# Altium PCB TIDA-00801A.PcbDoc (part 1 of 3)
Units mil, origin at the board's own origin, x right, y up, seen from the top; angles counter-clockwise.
Board outline 5000 x 3000 mil, 6 copper layers (Top Layer, Signal Layer 1, Signal Layer 2, Signal Layer 3, Signal Layer 4, Bottom Layer), stack 60.502 mil thick; 195 components, 95 nets, 602 pads, 757 vias.
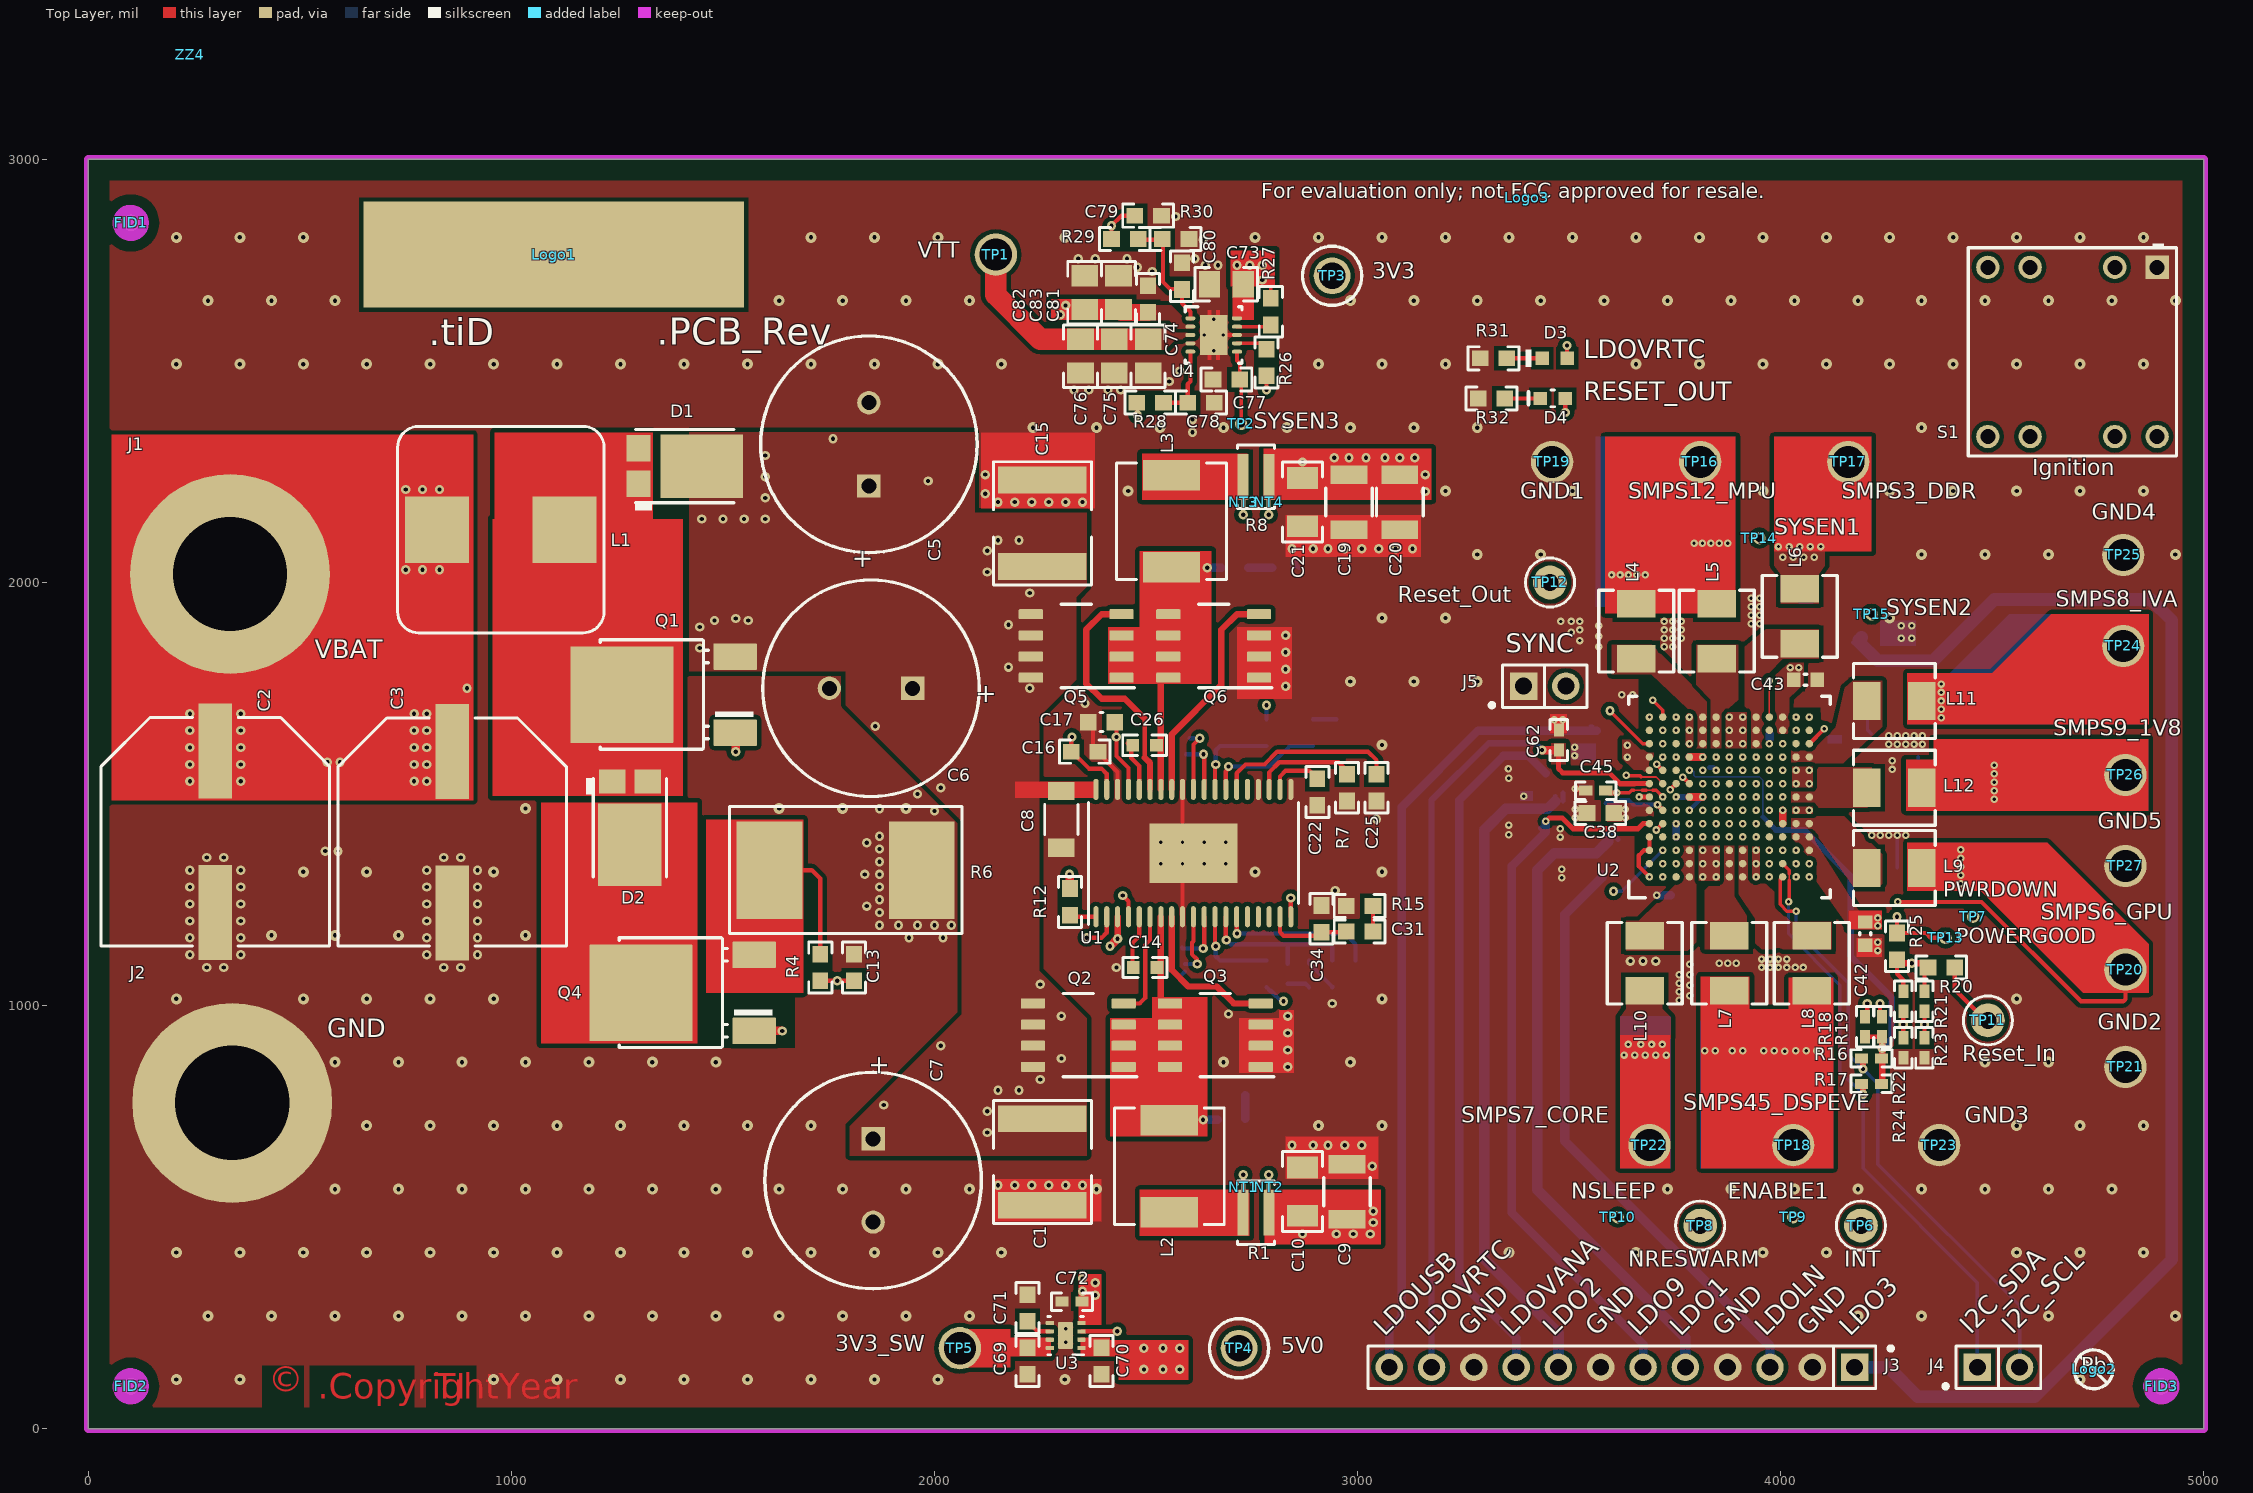
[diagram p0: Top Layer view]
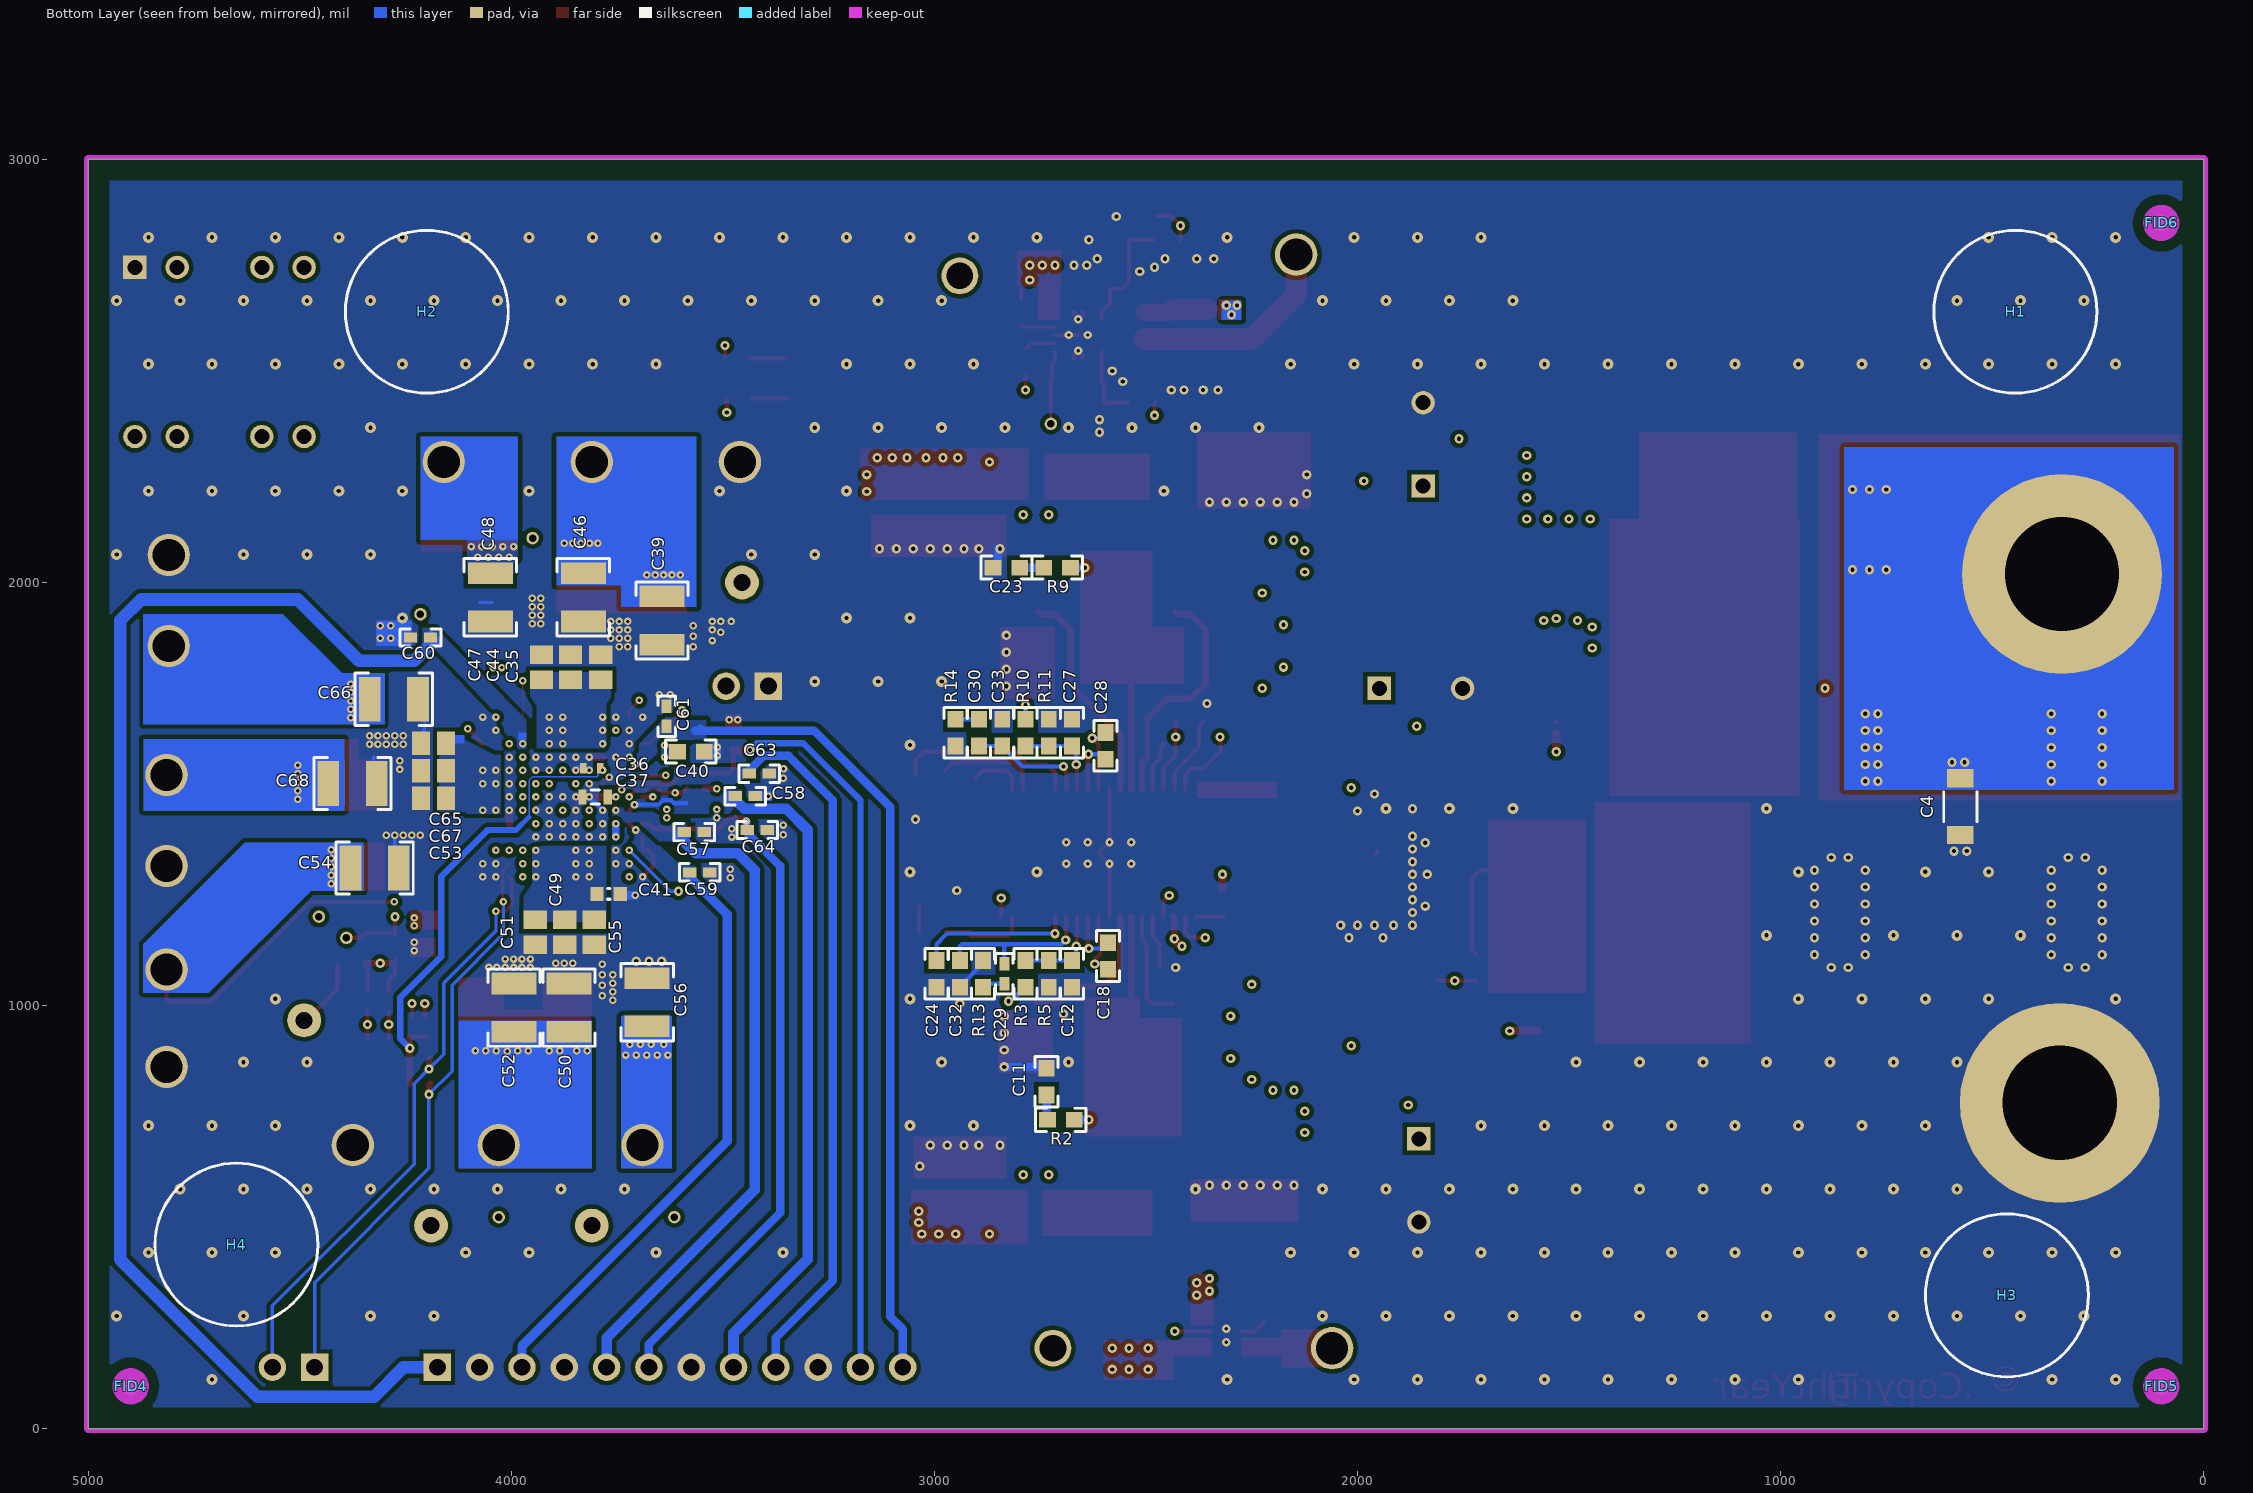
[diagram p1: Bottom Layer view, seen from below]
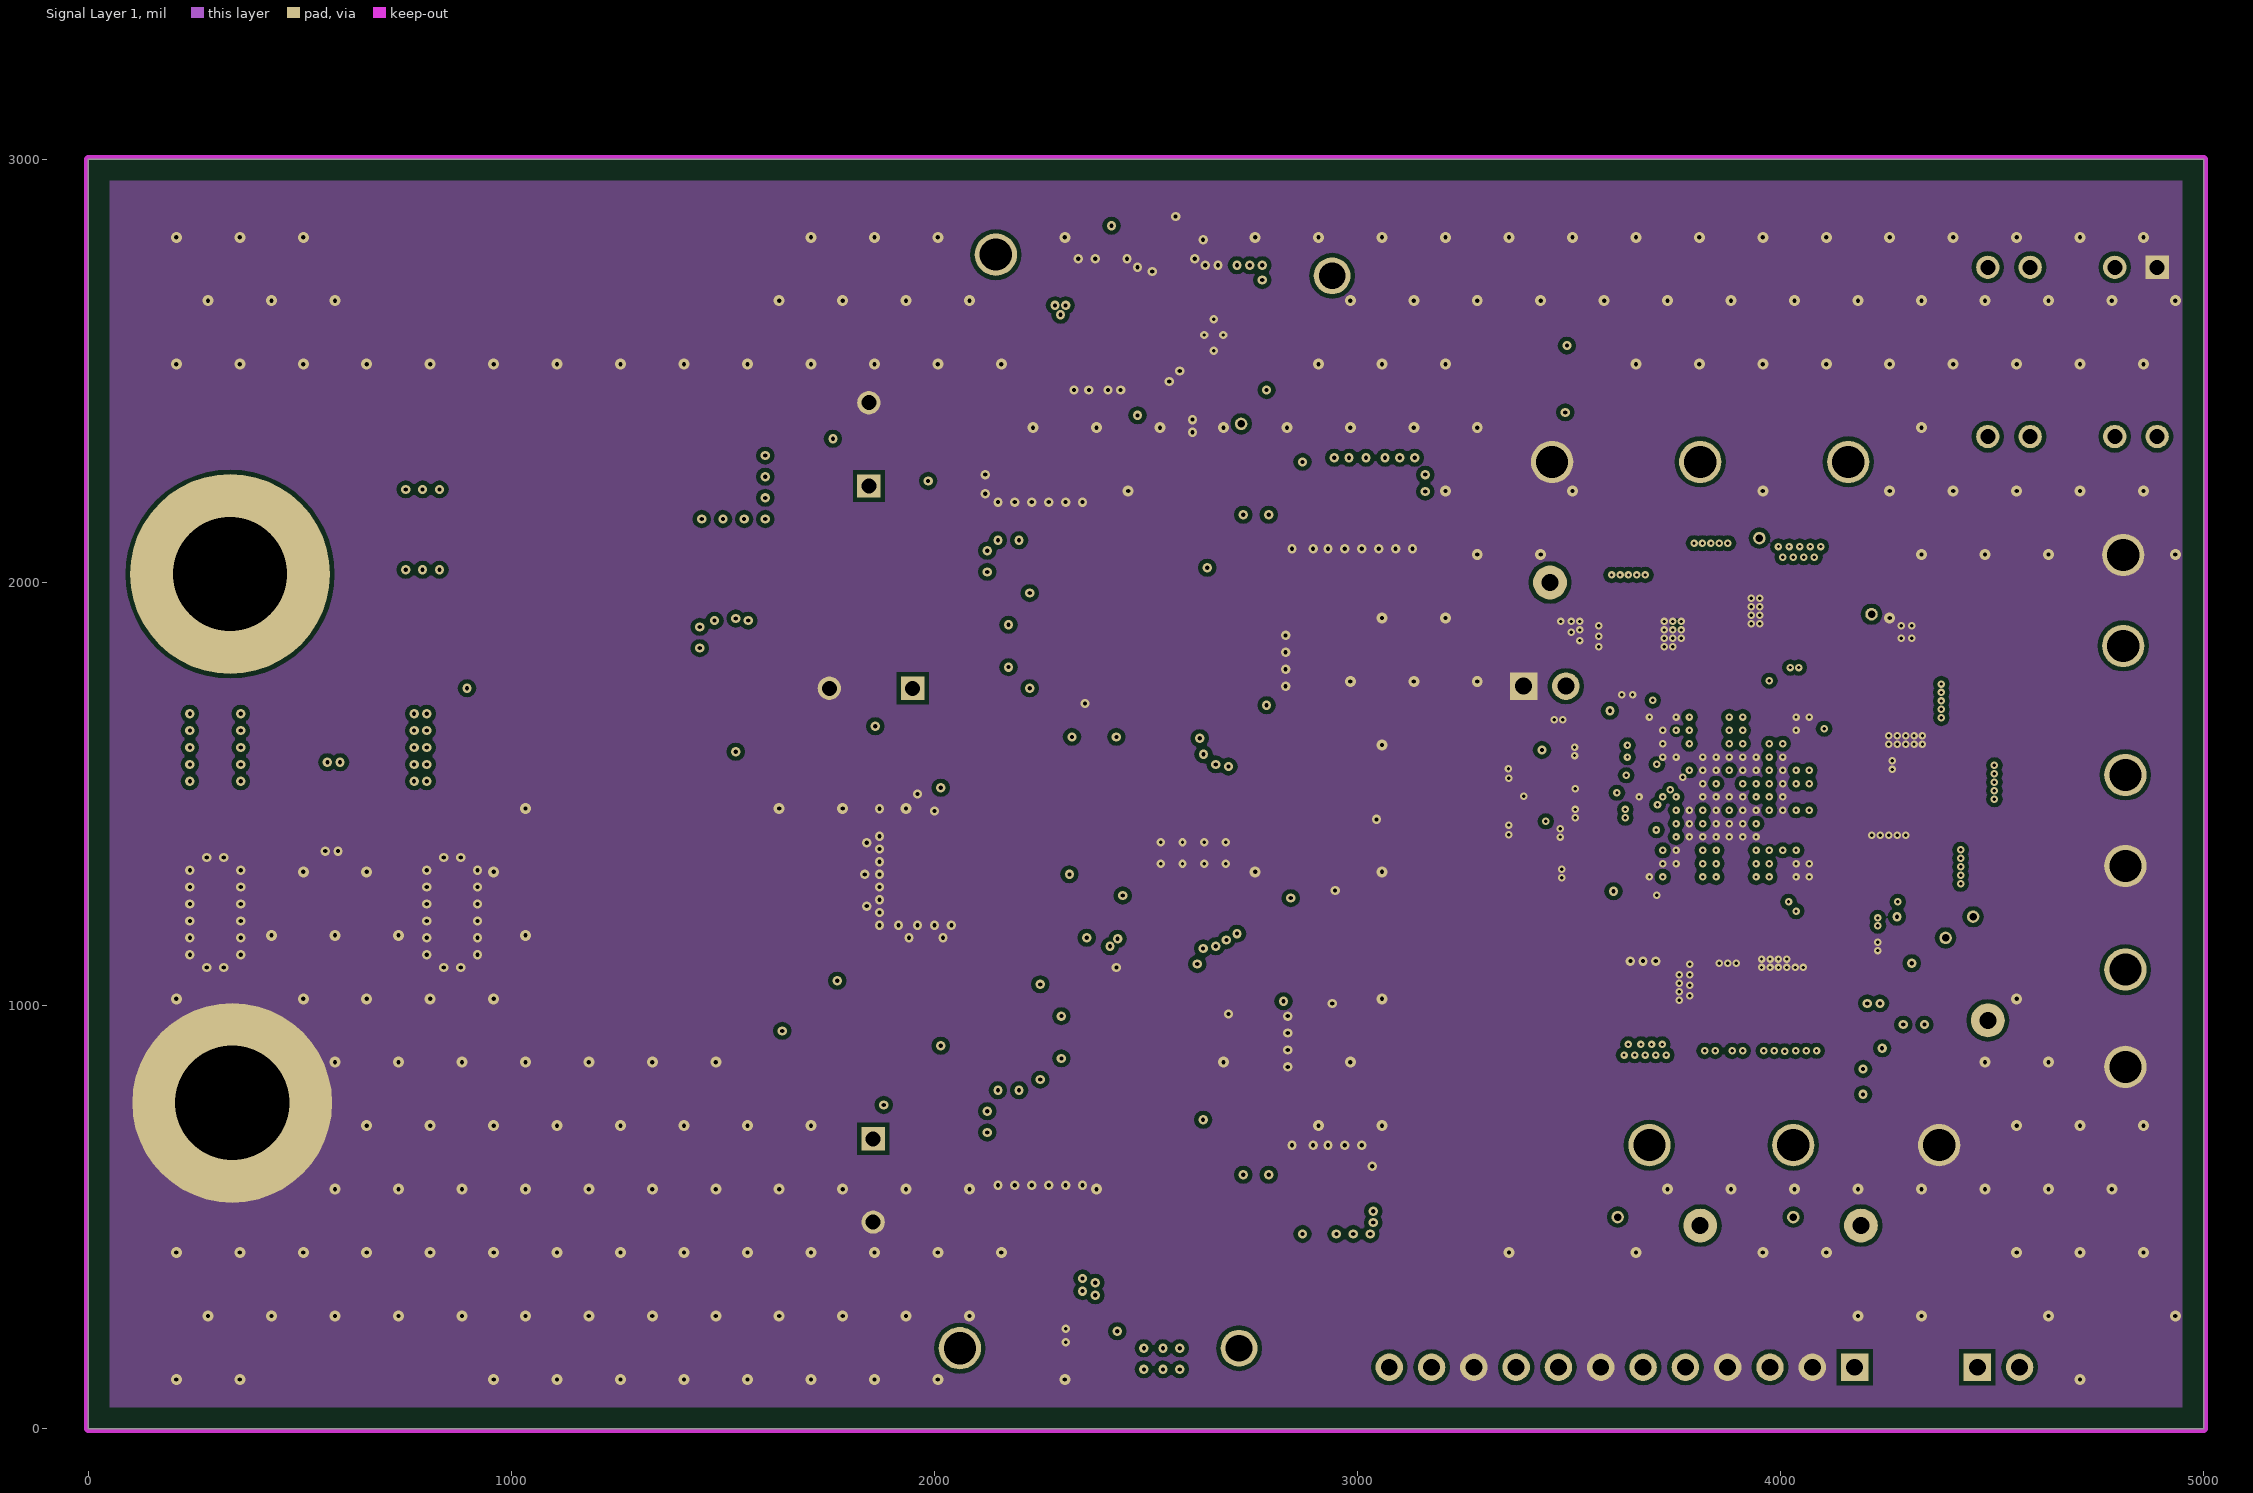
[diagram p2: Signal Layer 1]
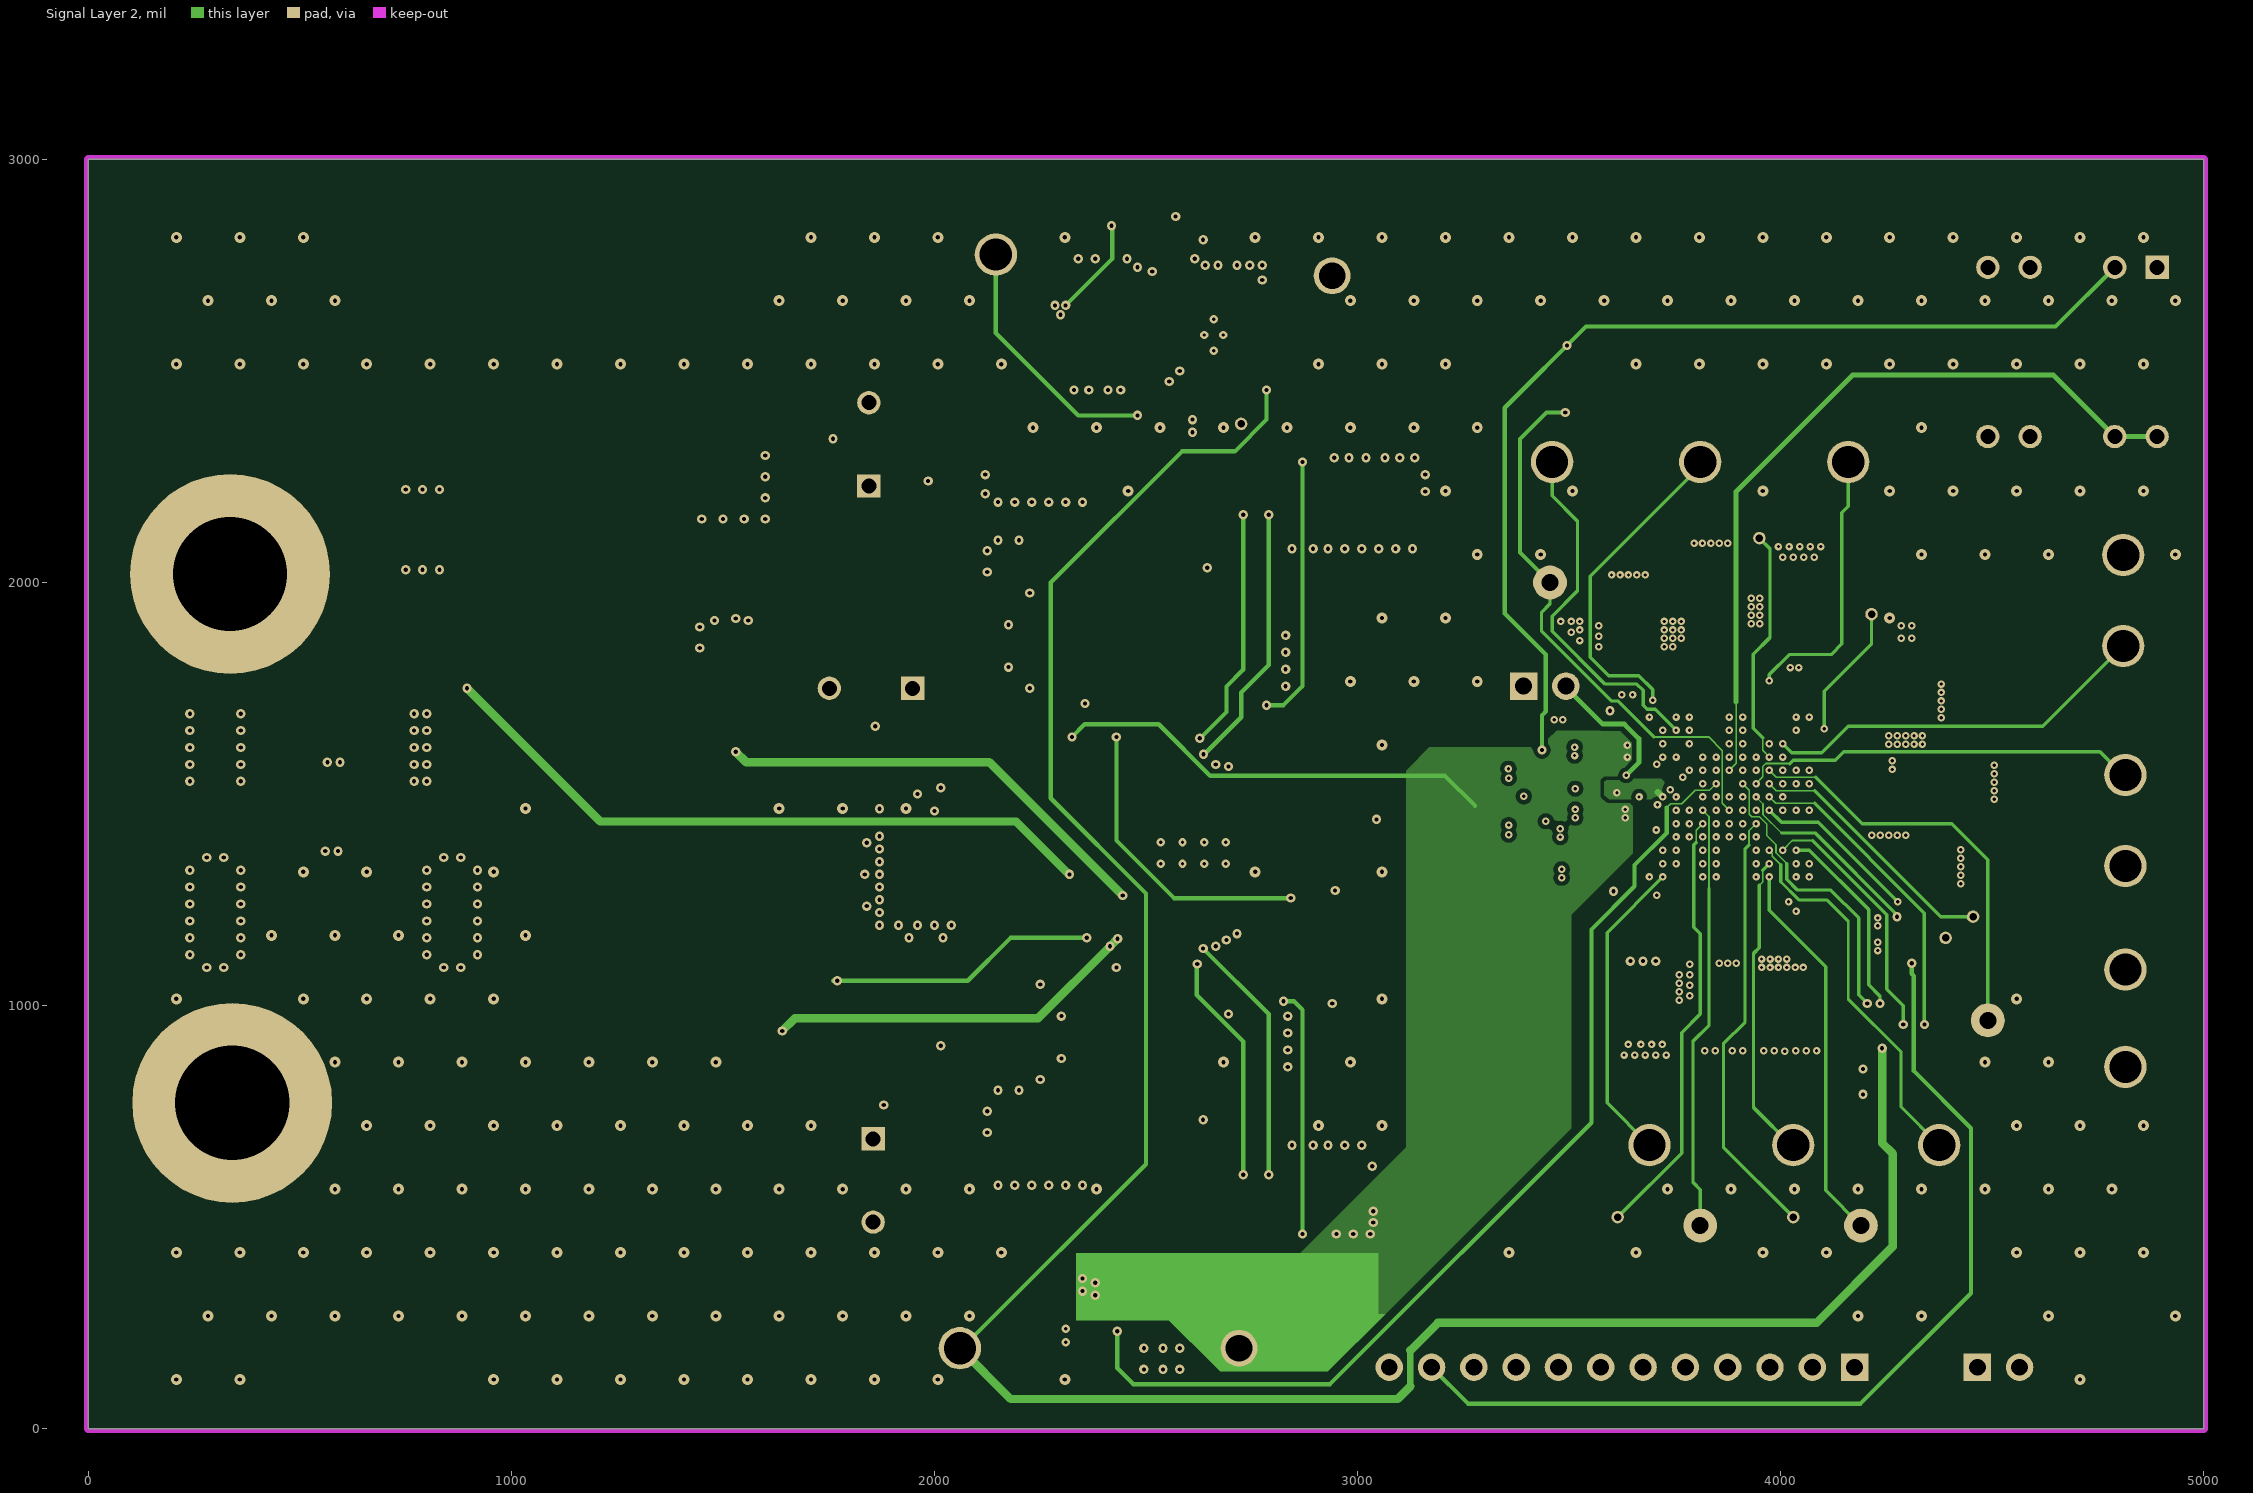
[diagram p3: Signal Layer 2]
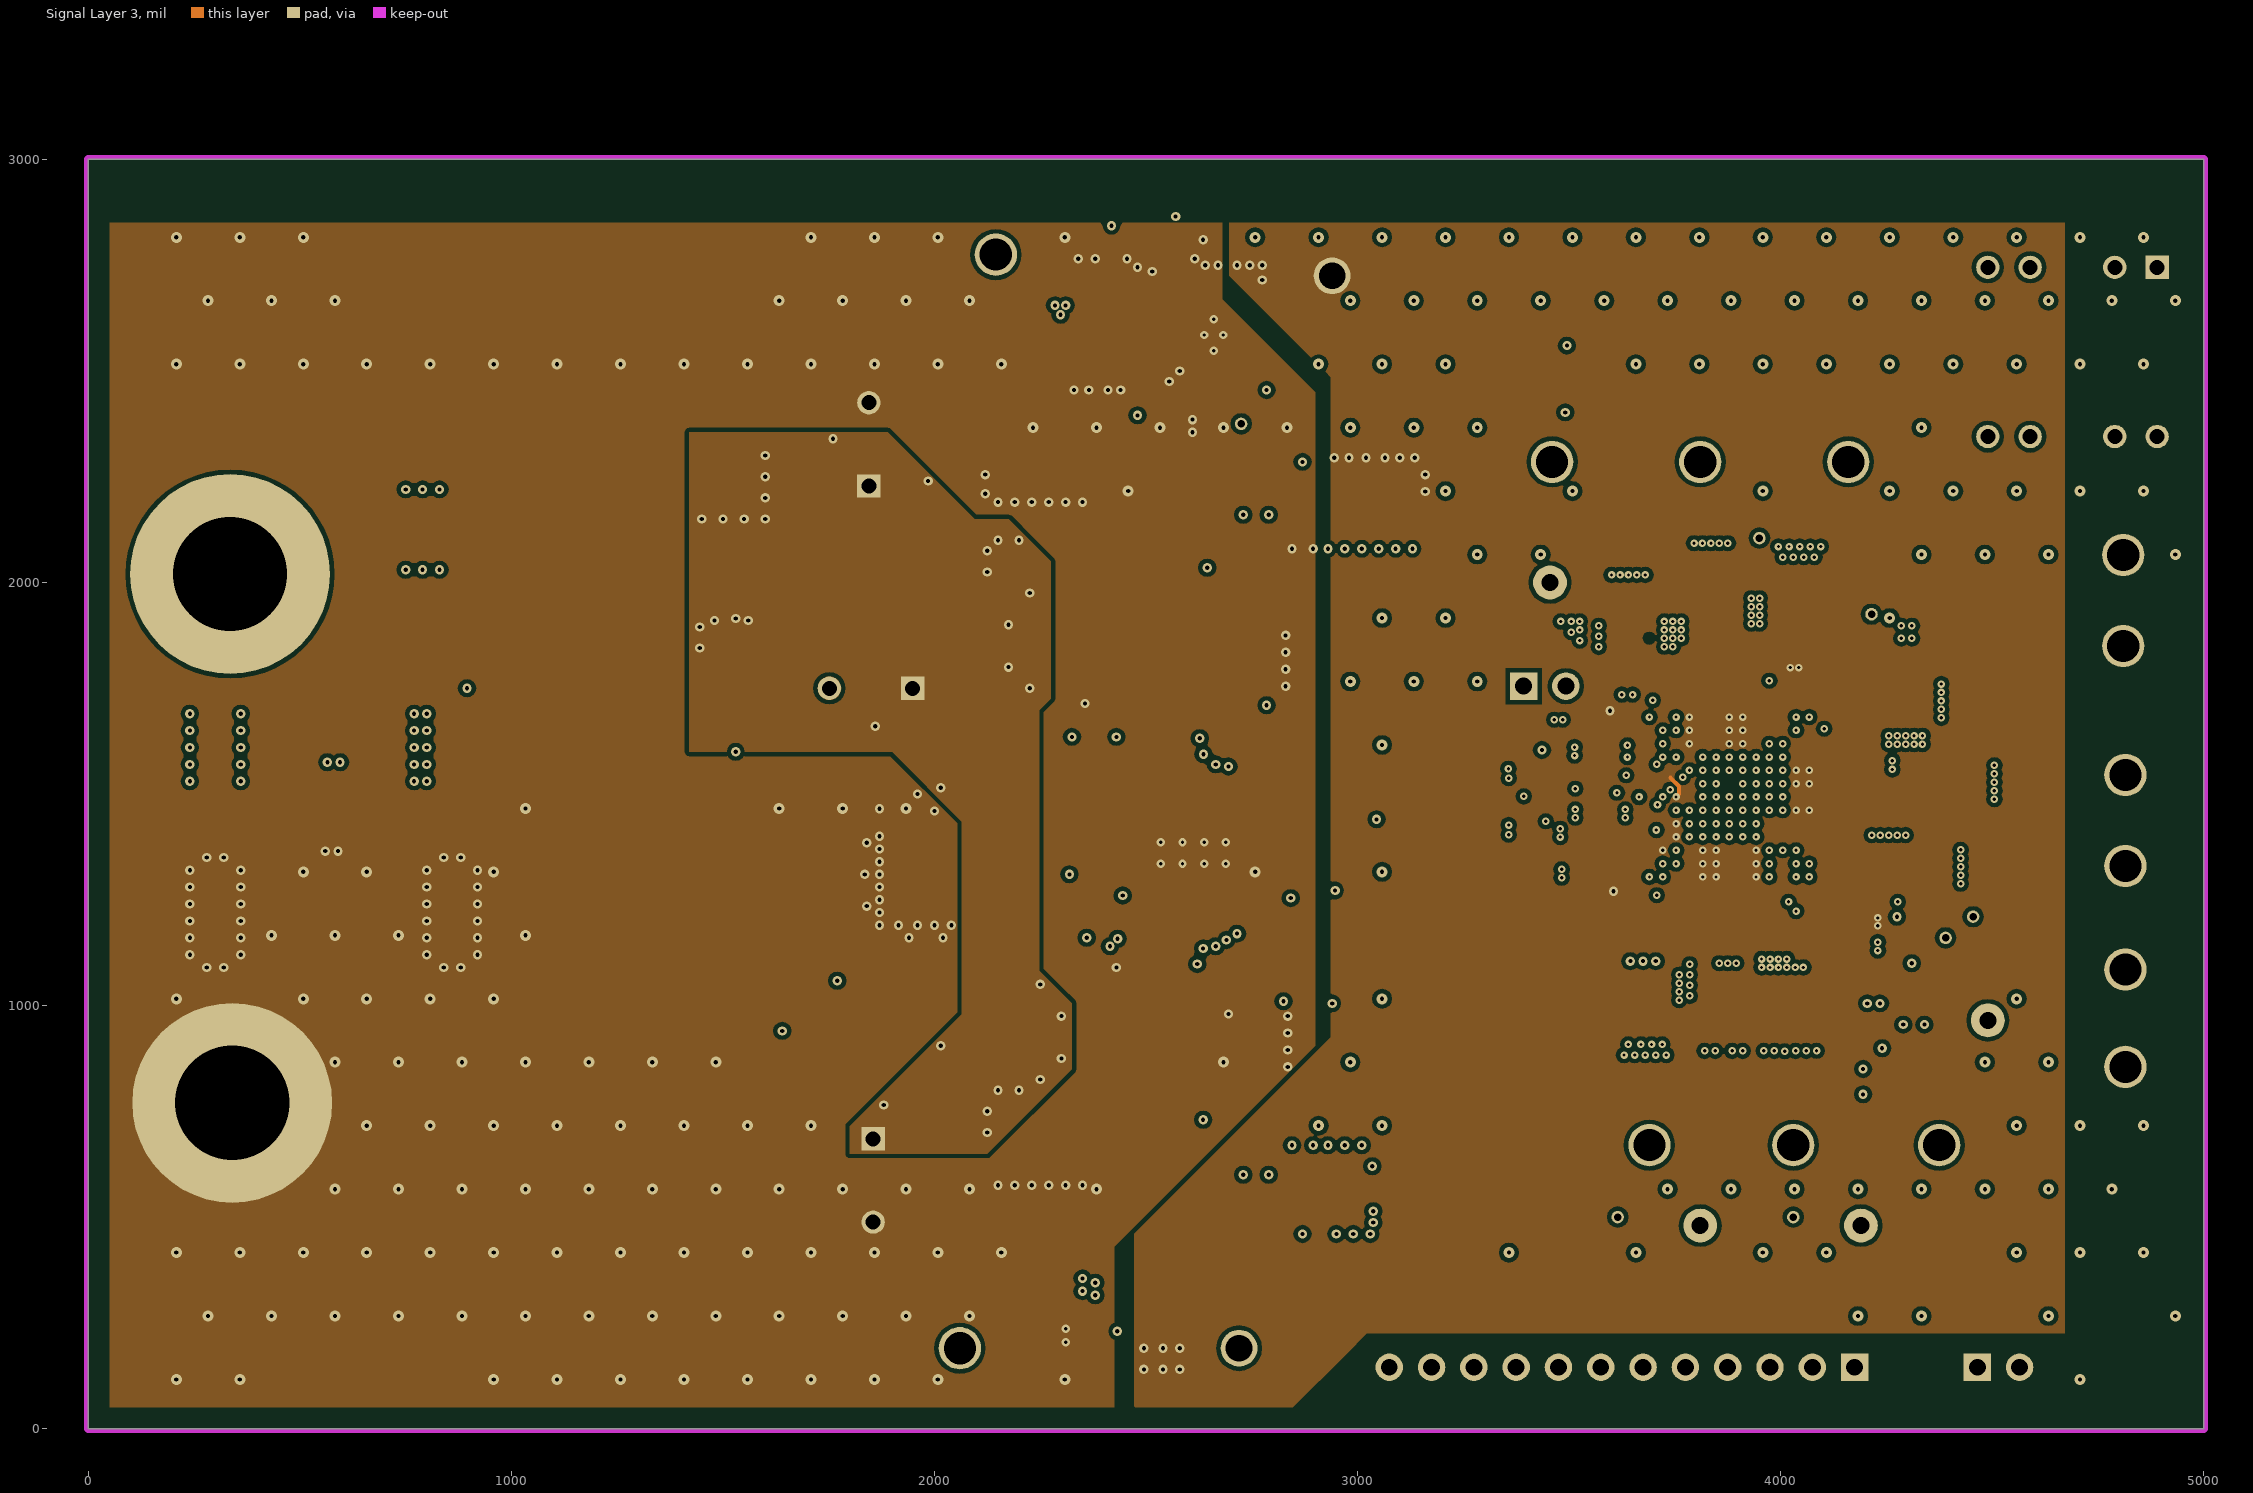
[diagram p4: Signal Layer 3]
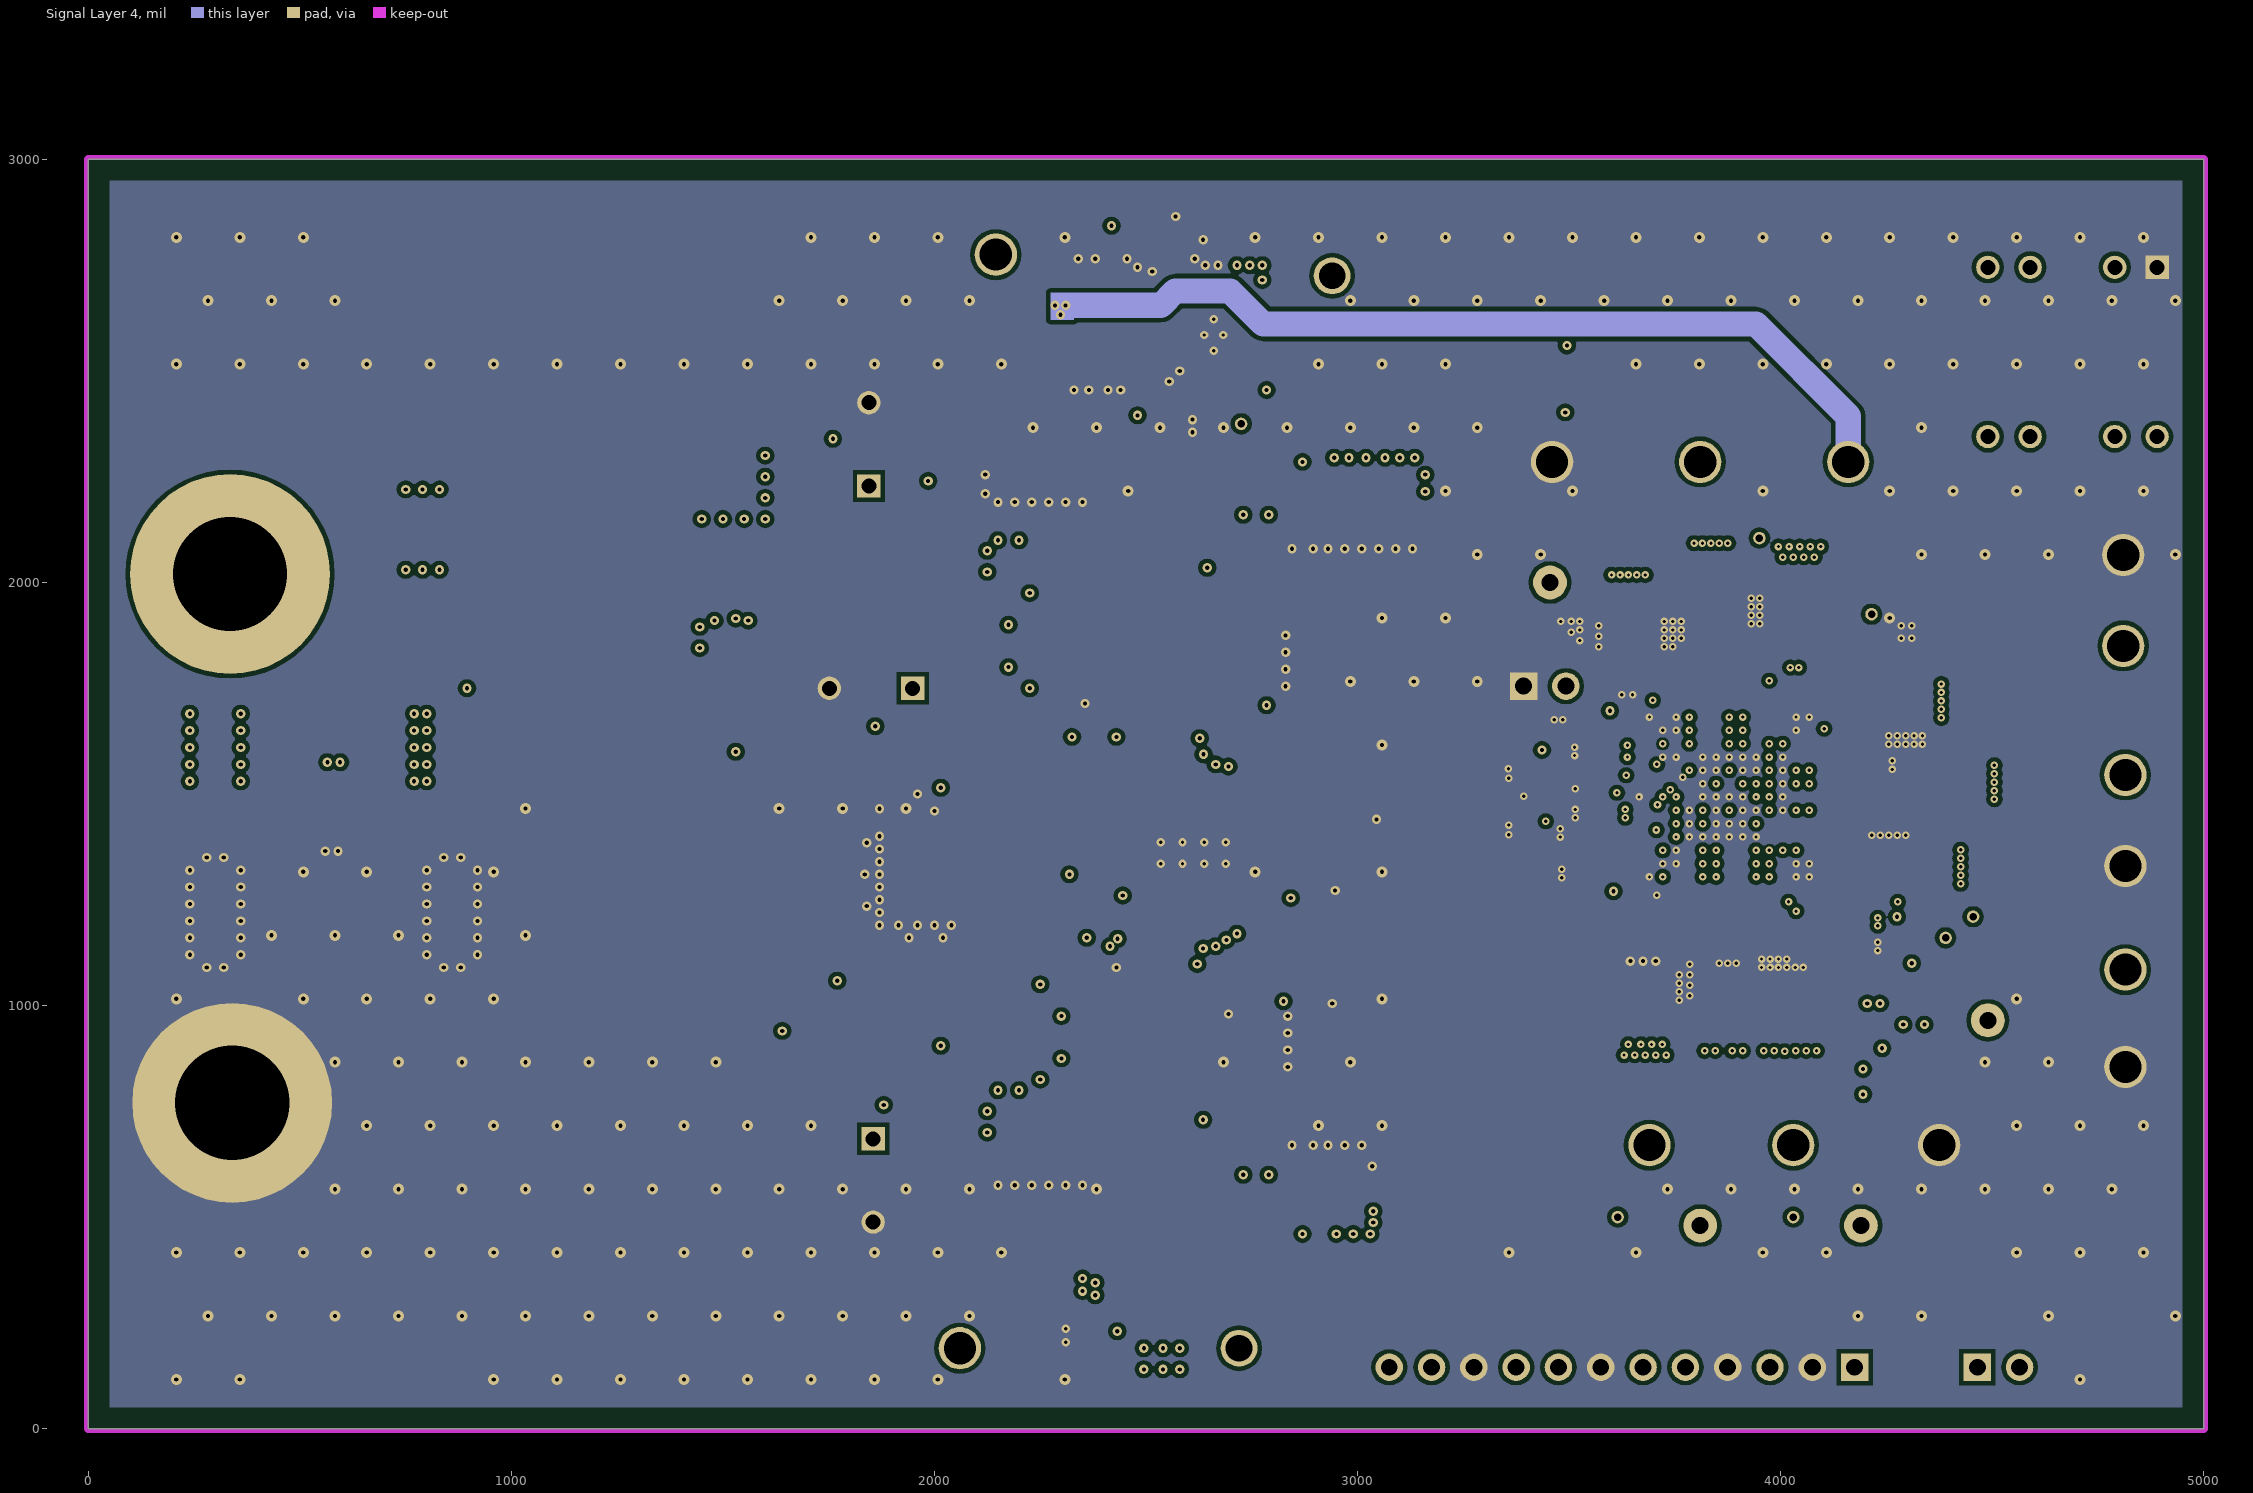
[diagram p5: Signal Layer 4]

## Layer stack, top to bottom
Top Solder: solder mask 0.4, Solder Resist, Dk 3.5
Top Layer: signal copper 1.417
Dielectric1: core 10, FR-4 High TG, Dk 4.8
Signal Layer 1: signal copper 1.417
Dielectric 2: prepreg 10, FR-4 High TG, Dk 4.8
Signal Layer 2: signal copper 1.417
Dielectric 3: core 12, FR-4 High TG, Dk 4.8
Signal Layer 3: signal copper 1.417
Dielectric 4: prepreg 10, FR-4 High TG, Dk 4.8
Signal Layer 4: signal copper 1.417
Dielectric 5: core 10, FR-4 High TG, Dk 4.8
Bottom Layer: signal copper 1.417
Bottom Solder: solder mask 0.4, Solder Resist, Dk 3.5

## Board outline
0,0 5000,0 5000,3000 0,3000

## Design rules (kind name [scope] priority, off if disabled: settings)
AcuteAngle [All] p1: minimum=4.50000000000000E+0001 checktracksonly=FALSE
AssemblyTestPointUsage [All] p1: valid=2
Clearance Clearance_Keepouts [((IsTrack Or IsArc) And Not InPoly) And IsFree and IsKeepOut vs ((IsTrack Or IsArc) And Not InPoly) And IsFree and IsKeepOut] p1: gap=0
Clearance Clearance_BoardEdge_MountingHoles [OnCopper and InComponentClass('Mounting Holes') vs IsKeepOut] p2: gap=40
Clearance Clearance_BoardEdge_Poly [OnCopper and InPoly vs IsKeepOut] p3: gap=25
Clearance Clearance_BoardEdge [OnCopper and Not InComponentClass('Logo') and not InComponentClass('FiducialMark') and not InRegion(1000,500,4000,800) and Not IsKeepout vs IsKeepOut] p4: gap=25
Clearance Clearance_Poly [InPolygon] p5: gap=10
Clearance [All] p6: gap=3.8
ComponentClearance ComponentClearance_NT [hasfootprint('Net-Tie_10milWide_30milLong')] p1: gap=0 collisioncheckmode=3 verticalgap=0 showdistances=FALSE
ComponentClearance ComponentClearance_MountingHoles_FiducialMarks [InComponentClass('Mounting Holes') vs InComponentClass('FiducialMark')] p2: gap=50 collisioncheckmode=3 verticalgap=10 showdistances=FALSE
ComponentClearance ComponentClearance_Shunt [InComponentClass('Header') vs InComponentClass('Shunt')] p3: gap=0 collisioncheckmode=3 verticalgap=0 showdistances=FALSE
ComponentClearance ComponentClearance_Logo [InComponentClass('Logo')] p4: gap=5 collisioncheckmode=3 verticalgap=5 showdistances=FALSE
ComponentClearance ComponentClearance_ScrewToNut [(HasFootprint('NY PMS 440 0025 PH')) vs (HasFootprint('Keystone_1902C'))] p5: gap=5 collisioncheckmode=3 verticalgap=10 showdistances=FALSE
ComponentClearance ComponentClearance_MountingHoles [InComponentClass('Mounting Holes')] p6: gap=150 collisioncheckmode=3 verticalgap=100000 showdistances=FALSE
ComponentClearance ComponentClearance_SmallPassives [HasFootprint('0201*') or HasFootprint('0402*') or HasFootprint('0508') or HasFootprint('0603*') or HasFootprint('0612') or HasFootprint('0805*') or HasFootprint('0815*') or HasFootprint('0830*') or HasFootprint('1206*') or HasFootprint('1210*') or HasFootprint('1808*') or HasFootprint('1812*') or HasFootprint('1825*') or HasFootprint('2010*') or HasFootprint('2220*') or HasFootprint('2225*') or HasFootprint('2512*') or HasFootprint('2728*') or HasFootprint('3518*') vs HasFootprint('0201*') or HasFootprint('0402*') or HasFootprint('0508') or HasFootprint('0603*') or HasFootprint('0612') or HasFootprint('0805*') or HasFootprint('0815*') or HasFootprint('0830*') or HasFootprint('1206*') or HasFootprint('1210*') or HasFootprint('1808*') or HasFootprint('1812*') or HasFootprint('1825*') or HasFootprint('2010*') or HasFootprint('2220*') or HasFootprint('2225*') or HasFootprint('2512*') or HasFootprint('2728*') or HasFootprint('3518*')] p7: gap=5 collisioncheckmode=3 verticalgap=5 showdistances=FALSE
ComponentClearance ComponentClearance_THtoSMT [IsThruComponent vs IsSMTComponent] p8: gap=30 collisioncheckmode=3 verticalgap=30 showdistances=FALSE
ComponentClearance ComponentClearance_THtoTH [IsThruComponent vs IsThruComponent] p9: gap=30 collisioncheckmode=3 verticalgap=30 showdistances=FALSE
ComponentClearance [All] p10: gap=20 collisioncheckmode=3 verticalgap=10 showdistances=FALSE
DiffPairsRouting [All] p1: maxlimit=100 minlimit=10 mostfreqgap=10 toplayer_minwidth=15 toplayer_maxwidth=15 toplayer_prefwidth=15 midlayer1_minwidth=15 midlayer1_maxwidth=15 midlayer1_prefwidth=15 midlayer2_minwidth=15 midlayer2_maxwidth=15 midlayer2_prefwidth=15 midlayer3_minwidth=15 midlayer3_maxwidth=15 midlayer3_prefwidth=15 midlayer4_minwidth=15 midlayer4_maxwidth=15 midlayer4_prefwidth=15 bottomlayer_minwidth=15 bottomlayer_maxwidth=15 bottomlayer_prefwidth=15 maxuncoupledlength=1000
FabricationTestPointUsage TestPointUsage [All] p1: valid=2 allowmultiple=FALSE
FabricationTestpoint Testpoint [All] p1: side=3 testpointundercomponent=TRUE minsize=40 maxsize=100 preferedsize=60 minholesize=0 maxholesize=40 preferedholesize=32 testpointgrid=1 allowsidetop=TRUE allowsidebottom=TRUE usegrid=TRUE gridtolerance=0.01
FanoutControl Fanout_LCC [IsLCC] p1: bgadir=Out bgaviamode=Centered fanoutstyle=Auto fanoutdirection=Alternating viagrid=1 // Fanout_LCC (Default Rule)
FanoutControl Fanout_BGA [IsBGA] p2: bgadir=Out bgaviamode=Centered fanoutstyle=Auto fanoutdirection=Alternating viagrid=1 // Fanout_BGA (Default Rule)
FanoutControl Fanout_Default [All] p4: bgadir=Out bgaviamode=Centered fanoutstyle=Auto fanoutdirection=Alternating viagrid=1 // Fanout_Default (Default Rule)
FanoutControl Fanout_Small [(CompPinCount < 5)] p5: bgadir=Out bgaviamode=Centered fanoutstyle=Auto fanoutdirection=OutThenIn viagrid=1 // Fanout_Small (Default Rule)
HoleSize [All] p1: absolutevalues=TRUE maxlimit=270 minlimit=7.8 maxpercent=80.000 minpercent=20.000
MinimumAnnularRing MinimumAnnularRing_ThermalPadVias [IsVia and InAnyComponent] p1: minimumring=5.91
MinimumAnnularRing [All] p2: minimumring=4.8
MinimumSolderMaskSliver MinimumSolderMaskSliver_Logo [InComponentClass('Logo') vs InComponentClass('Logo')] p1: minsoldermaskwidth=0.7
MinimumSolderMaskSliver [All] p2: minsoldermaskwidth=3.94
PlaneConnect [All] p1: planeconnectstyle=Relief reliefexpansion=10 reliefentries=4 reliefconductorwidth=10 reliefairgap=10
PolygonConnect [All] p1: connectstyle=Direct reliefconductorwidth=10 reliefentries=4 polygonreliefangle="90 Angle" airgapwidth=10
RoutingVias ThermalPadVias [IsVia and InAnyComponent] p1: holewidth=7.87 width=19.68 viastyle="Through Hole" minholewidth=7.87 minwidth=19.68 maxholewidth=12.99 maxwidth=23.62
RoutingVias [All] p2: holewidth=10 width=22 viastyle="Through Hole" minholewidth=7.8 minwidth=17 maxholewidth=40 maxwidth=65
SilkToBoardRegionClearance [Not ((IsComment or IsDesignator) And (Hide <> 'False')) and not InRegion(1000,500,4000,800)] p1 off:
SilkToSilkClearance SilkToSilkClearance_Pb-FreeLogo [(HasFootprint('Pb-Free_Overlay_Medium') OR HasFootprint('Pb-Free_Overlay_Small')) vs (HasFootprint('Pb-Free_Overlay_Medium') OR HasFootprint('Pb-Free_Overlay_Small'))] p1: silktosilkclearance=0
SilkToSilkClearance [All] p2: silktosilkclearance=3
SilkToSolderMaskClearance "Silk to Solder Mask Opening" [All] p1: minsilkscreentomaskgap=1 clearancetoexposedcopper=FALSE
SolderMaskExpansion [All] p1: expansion=1.97
UnpouredPolygon [All] p1: allowunpoured=FALSE
Width [All] p1: maxlimit=100 minlimit=4 preferedwidth=10 checkconnectedcopper=TRUE
14 further rules are at their usual default settings.

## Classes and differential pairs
component class TIDA-00801A_TPS51200: C73 C74 C75 C76 C77 C78 C79 C80 C81 C82 C83 R26 R27 R28 R29 R30 TP1 TP2 U4
component class TIDA-00801A_TPS22965: C69 C70 C71 C72 TP3 TP4 TP5 U3
component class TIDA-00801A_O9039A360: C35 C36 C37 C38 C39 C40 C41 C42 C43 C44 C45 C46 C47 C48 C49 C50 C51 C52 C53 C54 C55 C56 C57 C58 C59 C60 C61 C62 C63 C64 C65 C66 C67 C68 D3 D4 J3 J4 J5 L4 L5 L6 L7 L8 L9 L10 L11 L12 R16 R17 R18 R19 R20 R21 R22 R23 R24 R25 R31 R32 S1 TP6 TP7 TP8 TP9 TP10 TP11 TP12 TP13 TP14 TP15 TP16 TP17 TP18 TP19 TP20 TP21 TP22 TP23 TP24 TP25 TP26 TP27 U2
component class TIDA-00801A_TPS43330: C1 C2 C3 C4 C5 C6 C7 C8 C9 C10 C11 C12 C13 C14 C15 C16 C17 C18 C19 C20 C21 C22 C23 C24 C25 C26 C27 C28 C29 C30 C31 C32 C33 C34 D1 D2 J1 J2 L1 L2 L3 NT1 NT2 NT3 NT4 Q1 Q2 Q3 Q4 Q5 Q6 R1 R2 R3 R4 R5 R6 R7 R8 R9 R10 R11 R12 R13 R14 R15 U1
component class Header: J3 J4 J5
component class AssemblyNote: ZZ1 ZZ2 ZZ3 ZZ4
component class FiducialMark: FID1 FID2 FID3 FID4 FID5 FID6
component class TIDA-00801A_Hardware: FID1 FID2 FID3 FID4 FID5 FID6 H1 H2 H3 H4 Logo1 Logo2 Logo3 ZZ1 ZZ2 ZZ3 ZZ4
component class Logo: Logo1

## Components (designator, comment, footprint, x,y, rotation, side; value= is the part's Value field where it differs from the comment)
C1 "CGA9N3X7R1H106K230KB" 2220 2255,630 r270 top
C2 "EEE-TK1J221AQ" SM_RADIAL_H13 300,1410.94 r270 top
C3 "EEE-TK1J221AQ" SM_RADIAL_H13 860,1410 r270 top
C4 "CL31B105JAHNNNE" 1206_190 575,1470 r270 bottom
C5 "EEU-FC1H561" FC_1250x2500 1845,2326.57 r90 top
C6 "EEU-FC1H561" FC_1250x2500 1850,1750 r180 top
C7 "EEU-FC1H561" FC_1250x2500 1855,586.57 r270 top
C8 "CL31B105JAHNNNE" 1206_190 2300,1440 r270 top
C9 "LMK325ABJ107MMHT" 1210_280 2975,560 r90 top
C10 "C1206C105K3RACTU" 1206 2870,560 r90 top
C11 "GRM1885C1E102JA01D" 0603 2735,820 r90 bottom
C12 "GRM1885C1H470JA01D" 0603 2675,1075 r270 bottom
C13 "C0603C471K5RACTU" 0603 1810,1090 r90 top
C14 "GRM188R61E224KA88D" 0603_HV 2498,1090 r180 top
C15 "CGA9N3X7R1H106K230KB" 2220 2255,2140 r270 top
C16 "C0603C104J3RACTU" 0603 2355,1600 r180 top
C17 "GRM188R61E475KE11D" 0603_095 2395,1670 r180 top
C18 "GRM188R71E103KA01D" 0603 2590,1117 r90 bottom
C19 "LMK325ABJ107MMHT" 1210_280 2980,2190 r270 top
C20 "LMK325ABJ107MMHT" 1210_280 3100,2190 r270 top
C21 "C1206C105K3RACTU" 1206 2870,2190 r270 top
C22 "GRM188R71H102KA01D" 0603 2905,1505 r90 top
C23 "GRM188R71H102KA01D" 0603 2830,2035 r0 bottom
C24 "GRM188R71E103KA01D" 0603 2995,1075 r270 bottom
C25 "GRM188R71E103KA01D" 0603 3045,1515 r270 top
C26 "GRM188R61E224KA88D" 0603_HV 2497,1615 r180 top
C27 "GRM1885C1H470JA01D" 0603 2675,1645 r90 bottom
C28 "GRM188R71E103KA01D" 0603 2596,1614 r90 bottom
C29 "C1005C0G1E681J" 0402 2835,1075 r270 bottom
C30 "C0603X102K5RACTU" 0603 2895,1645 r90 bottom
C31 "06033C123JAT2A" 0603 3005,1175 r0 top
C32 "C1608C0G1H180J" 0603 2940,1075 r270 bottom
C33 "06035A270JAT2A" 0603 2840,1645 r90 bottom
C34 "GRM1885C1H121JA01D" 0603 2915,1205 r90 top
C35 "C2012X5R1E475K125AB" 0805L 3789,1800 r270 bottom
C36 "GCM155R71C104KA55D" 0402S 3810,1561 r180 bottom
C37 "EMK107BBJ106MA-T" 0603S 3802,1493 r0 bottom
C38 "GRM188R61C225KAAD" 0603 3574,1455 r0 top
C39 "GRM32ER71A476KE15L" 1210 3644,1910 r270 bottom
C40 "GRM188R61C225KAAD" 0603 3576,1600 r180 bottom
C41 "GRM188R61C225KAAD" 0603L 3770,1264 r180 bottom
C42 "GRM188R61C225KAAD" 0603L 4200,1170 r270 top
C43 "GRM188R61C225KAAD" 0603L 4059,1770 r0 top
C44 "C2012X5R1E475K125AB" 0805L 3860.56,1800 r270 bottom
C45 "GCM155R71C104KA55D" 0402 3563,1508 r180 top
C46 "GRM32ER71A476KE15L" 1210 3830,1965 r270 bottom
C47 "C2012X5R1E475K125AB" 0805L 3929,1800 r270 bottom
C48 "GRM32ER71A476KE15L" 1210 4050,1965 r270 bottom
C49 "C2012X5R1E475K125AB" 0805L 3874,1173 r90 bottom
C50 "GRM32ER71A476KE15L" 1210 3864.14,995 r90 bottom
C51 "C2012X5R1E475K125AB" 0805L 3944,1173 r90 bottom
C52 "GRM32ER71A476KE15L" 1210 3994,995 r90 bottom
C53 "C2012X5R1E475K125AB" 0805L 4184,1490 r180 bottom
C54 "GRM32ER71A476KE15L" 1210 4323.26,1325 r0 bottom
C55 "C2012X5R1E475K125AB" 0805L 3804,1173 r90 bottom
C56 "GRM32ER71A476KE15L" 1210 3679,1007.84 r90 bottom
C57 "GRM155R60J225ME15D" 0402 3568,1410 r180 bottom
C58 "GRM155R60J225ME15D" 0402 3447,1495 r180 bottom
C59 "GRM155R60J225ME15D" 0402 3555,1315 r180 bottom
C60 "GRM155R60J225ME15D" 0402 4215,1870 r0 bottom
C61 "GRM155R60J225ME15D" 0402 3632.95,1683.93 r90 bottom
C62 "GRM155R60J225ME15D" 0402 3476,1627.62 r90 top
C63 "GRM155R60J225ME15D" 0402 3414,1548 r180 bottom
C64 "GRM155R60J225ME15D" 0402 3419,1415 r180 bottom
C65 "C2012X5R1E475K125AB" 0805L 4184,1620 r180 bottom
C66 "GRM32ER71A476KE15L" 1210 4278,1724 r0 bottom
C67 "C2012X5R1E475K125AB" 0805L 4184,1555 r180 bottom
C68 "GRM32ER71A476KE15L" 1210 4375.5,1525 r0 bottom
C69 "GRM188R61C104KA01D" 0603 2220,160 r270 top
C70 "GRM185R61C105KE44D" 0603 2395,160 r270 top
C71 "C1608X7R1H221K" 0603 2220,285 r90 top
C72 "GRM155R61A103KA01D" 0402 2325,300 r180 top
C73 "C2012X5R1E106K125AB" 0805_HV 2690,2705 r180 top
C74 "GRM21BR70J106KE76L" 0805_HV 2505,2535 r90 top
C75 "GRM21BR70J106KE76L" 0805_HV 2425,2535 r270 top
C76 "GRM21BR70J106KE76L" 0805_HV 2345,2535 r270 top
C77 "CGA3E2X8R1E104K080AA" 0603 2690,2480 r180 top
C78 "GRM1885C2A100JA01D" 0603 2630,2425 r0 top
C79 "GRM1885C1H102FA01J" 0603 2505,2867 r180 top
C80 "GRM1885C1H102FA01J" 0603 2585,2724 r270 top
C81 "GRM1885C1H102FA01J" 0603 2505,2670 r270 top
C82 "GRM21BR70J106KE76L" 0805_HV 2355,2685 r90 top
C83 "GRM21BR70J106KE76L" 0805_HV 2435,2685 r90 top
D1 "PMEG045V150EPDAZ" SOT1289 1410,2275 r90 top
D2 "PMEG045V150EPDAZ" SOT1289 1280,1420 r0 top
D3 "SML-LX0603SRW-TR" SML-LX0603SRW_SuperRed 3466.5,2530 r180 top
D4 "LG L29K-G2J1-24-Z" "LG L29K_GREEN" 3461.5,2435 r180 top
FID1 "Fiducial" Fiducial10-20 100,2850 r0 top
FID2 "Fiducial" Fiducial10-20 100,100 r0 top
FID3 "Fiducial" Fiducial10-20 4900,100 r0 top
FID4 "Fiducial" Fiducial10-20 4900,100 r90 bottom
FID5 "Fiducial" Fiducial10-20 100,100 r90 bottom
FID6 "Fiducial" Fiducial10-20 100,2850 r90 bottom
H1 "SJ61A2" Bumpon_SJ61A2 445,2640 r180 bottom
H2 "SJ61A2" Bumpon_SJ61A2 4200,2640 r180 bottom
H3 "SJ61A2" Bumpon_SJ61A2 465,315 r180 bottom
H4 "SJ61A2" Bumpon_SJ61A2 4650,435 r180 bottom
J1 "SPC15363" Tenma_SPC15363 335,2020 r0 top
J2 "SPC15354" Tenma_SPC15354 340,770 r0 top
J3 "TSW-112-07-G-S" TSW-112-07-G-S 3625,145 r180 top
J4 "HTSW-102-07-G-S" Samtec_HTSW-102-07-G-S 4515,145 r0 top
J5 "SYNC" Samtec_HTSW-102-07-G-S 3442.48,1755 r0 top
L1 "744325180" WE-HC6 975,2125 r0 top
L2 "IHLP2525CZER100M01" IHLP-2525CZ 2555,620 r270 top
L3 "IHLP2525CZER4R7M01" IHLP-2525CZ 2560,2145 r90 top
L4 "IHLP1616ABER1R0M01" IHLP-1616AB 3659,1884.96 r90 top
L5 "IHLP1616ABER1R0M01" IHLP-1616AB 3849,1885 r90 top
L6 "IHLP1616ABER1R0M01" IHLP-1616AB 4045,1920 r90 top
L7 "IHLP1616ABER1R0M01" IHLP-1616AB 3879,1100 r270 top
L8 "IHLP1616ABER1R0M01" IHLP-1616AB 4074,1100 r270 top
L9 "IHLP1616ABER1R0M01" IHLP-1616AB 4269,1325 r0 top
L10 "IHLP1616ABER1R0M01" IHLP-1616AB 3679,1100 r270 top
L11 "IHLP1616ABER1R0M01" IHLP-1616AB 4269,1720 r0 top
L12 "IHLP1616ABER1R0M01" IHLP-1616AB 4268.96,1515 r0 top
Logo1 "Texas Instruments" TI_Stacked_SolderMask_Small 1100,2775 r0 top
Logo2 "Pb-Free Symbol" Pb-Free_Overlay_Small 4740,140 r0 top
Logo3 "FCC disclaimer" FCC_disclaimer 3400,2910 r0 top
NT1 "Net-Tie" Net-Tie_10milWide_30milLong 2730,570 r270 top net-tie
NT2 "Net-Tie" Net-Tie_10milWide_30milLong 2790,570 r270 top net-tie
NT3 "Net-Tie" Net-Tie_10milWide_30milLong 2730,2190 r90 top net-tie
NT4 "Net-Tie" Net-Tie_10milWide_30milLong 2790,2190 r90 top net-tie
Q1 "SUD50P06-15L-E3" DPAK 1395,1735 r180 top
Q2 "Si4840BDY-T1-GE3" SOIC-8 2340,930 r180 top
Q3 "Si4840BDY-T1-GE3" SOIC-8 2664,930 r180 top
Q4 "IRLR3114ZTRPBF" DPAK 1440,1030 r180 top
Q5 "Si4840BDY-T1-GE3" SOIC-8 2335,1850 r180 top
Q6 "Si4840BDY-T1-GE3" SOIC-8 2660,1850 r180 top
R1 "PRL1632-R022-F-T1" 0612 2760,510 r0 top
R2 "CRCW060310R0FKEA" 0603 2701.5,730 r180 bottom
R3 "CRCW0603432KFKEA" 0603 2785,1075 r270 bottom
R4 "ERJ-3EKF1501V" 0603 1730,1090 r270 top
R5 "CRCW060382K5FKEA" 0603 2730,1075 r90 bottom
R6 "WSR3R0150FEA" 4527 1790,1320 r180 top
R7 "RG1608P-4992-B-T5" 0603 2975,1515 r90 top
R8 "PRL1632-R015-F-T1" 0612 2760,2250 r0 top
R9 "CRCW060310R0FKEA" 0603 2710,2035 r180 bottom
R10 "CRCW0603255KFKEA" 0603 2785,1645 r90 bottom
R11 "CRCW060382K5FKEA" 0603 2730,1645 r270 bottom
R12 "CRCW06031K00JNEA" 0603 2320,1245 r270 top
R13 "RC0603JR-0739KL" 0603 2885,1075 r270 bottom
R14 "RT0603DRD0727KL" 0603 2950,1645 r90 bottom
R15 "RC0603FR-0710KL" 0603 3005,1235 r0 top
R16 "CRCW04022K20JNED" 0402 4215,875 r0 top
R17 "CRCW04022K20JNED" 0402 4215,815 r0 top
R18 "CRCW04022K20JNED" 0402 4200,950 r270 top
R19 "CRCW04022K20JNED" 0402 4240,950 r270 top
R20 "RC0603FR-0710KL" 0603 4380,1090 r0 top
R21 "RC0402JR-070RL" 0402 4340,1010 r90 top
R22 "RC0402JR-070RL" 0402 4290,1010 r90 top
R23 "RC0402JR-070RL" 0402 4340,900 r90 top
R24 "RC0402JR-070RL" 0402 4290,900 r90 top
R25 "RC0603FR-0710KL" 0603 4275,1140 r270 top
R26 "CRCW060310K0FKEA" 0603 2785,2520 r270 top
R27 "CRCW0603100KJNEA" 0603 2795,2640 r90 top
R28 "TNPW060310R0BEEA" 0603 2510,2425 r180 top
R29 "CRCW060310K0FKEA" 0603 2450,2812 r0 top
R30 "CRCW060310K0FKEA" 0603 2570,2812 r0 top
R31 "RC0603FR-0749R9L" 0603 3321.5,2530 r0 top
R32 "CRCW0603806RFKEA" 0603 3316.5,2435 r0 top
S1 "Ignition" SW_15451 4690,2545 r270 top
TP1 "VTT" Mill-Max_2505-2 2145,2775 r90 top
TP2 "SYSEN3" TP_H045P075 2725,2375 r90 top
TP3 "3V3" Keystone5006 2940,2725 r270 top
TP4 "5V0" Keystone5006 2720,190 r270 top
TP5 "3V3_SW" Mill-Max_2505-2 2060,190 r270 top
TP6 "INT" Keystone5002 4190,480 r0 top
TP7 "PWRDOWN" TP_H045P075 4455,1210 r180 top
TP8 "NRESWARM" Keystone5002 3810,480 r90 top
TP9 "ENABLE1" TP_H045P075 4030,500 r90 top
TP10 "NSLEEP" TP_H045P075 3615,500 r180 top
TP11 "Reset_In" Keystone5002 4490,965 r0 top
TP12 "Reset_Out" Keystone5002 3455,2000 r0 top
TP13 "POWERGOOD" TP_H045P075 4390,1160 r180 top
TP14 "SYSEN1" TP_H045P075 3950,2105 r180 top
TP15 "SYSEN2" TP_H045P075 4215,1925 r180 top
TP16 "SMPS12_MPU" Mill-Max_2505-2 3810,2285 r180 top
TP17 "SMPS3_DDR" Mill-Max_2505-2 4160,2285 r180 top
TP18 "SMPS45_DSPEVE" Mill-Max_2505-2 4030,670 r180 top
TP19 "GND1" Mill-Max_2505-2 3460,2285 r90 top
TP20 "SMPS6_GPU" Mill-Max_2505-2 4815,1085 r180 top
TP21 "GND2" Mill-Max_2505-2 4815,855 r90 top
TP22 "SMPS7_CORE" Mill-Max_2505-2 3690,670 r180 top
TP23 "GND3" Mill-Max_2505-2 4375,670 r0 top
TP24 "SMPS8_IVA" Mill-Max_2505-2 4810,1850 r180 top
TP25 "GND4" Mill-Max_2505-2 4810,2065 r90 top
TP26 "SMPS9_1V8" Mill-Max_2505-2 4815,1545 r180 top
TP27 "GND5" Mill-Max_2505-2 4815,1330 r90 top
U1 "TPS43330AQDAPRQ1" DAP0038B_N 2612,1360.5 r90 top
U2 "O9039A360IZWSRQ1" ZWS0169A 3879,1492.99 r90 top
U3 "TPS22965TDSGRQ1" DSG0008A 2310,220 r180 top
U4 "TPS51200QDRCRQ1" DRC0010A 2660,2585 r0 top
ZZ1 "Place washers H5 & H6 over threaded studs of banana jacks J1 & J2 before assembling onto board to increase clearance below them." AssemblyNote 240,3509 r0 top
ZZ2 "These assemblies are ESD sensitive, ESD precautions shall be observed." AssemblyNote 240,3424.11 r0 top
ZZ3 "These assemblies must be clean and free from flux and all contaminants. Use of no clean flux is not acceptable." AssemblyNote 240,3335.56 r0 top
ZZ4 "These assemblies must comply with workmanship standards IPC-A-610 Class 2, unless otherwise specified." AssemblyNote 240,3247 r0 top

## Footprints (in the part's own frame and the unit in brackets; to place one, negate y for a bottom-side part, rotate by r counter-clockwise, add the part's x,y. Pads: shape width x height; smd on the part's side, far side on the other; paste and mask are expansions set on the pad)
0402 [mm] "0402 from SM-752 data"
  rect 0.8x0.6 smd: 1(-0.6,0) 2(0.6,0)
  silkscreen extent -1.22,-0.52 1.22,0.52, body extent -0.55,-0.3 0.55,0.3, height 0.6
0402S [mil] "Based on C0402S footprint from PADS legacy"
  rect 15x24 smd mask+0: 1(-20,0) 2(20,0)
  body extent -22,-12 22,12, height 24
0603 [mm] "0603 from SM-752 data"
  rect 1x0.95 smd: 1(-0.8,0) 2(0.8,0)
  silkscreen extent -1.52,-0.69 1.52,0.69, body extent -0.87,-0.47 0.87,0.47, height 0.85
0603_095 [mm] "0603_095"
  rect 1x1 smd: 1(-0.8,0) 2(0.8,0)
  silkscreen extent -0.1,-0.58 0.1,0.58, body extent -0.87,-0.48 0.87,0.48, height 0.95
0603_HV [mil] "Ernesto recommended land pattern.  26 mil between pads."
  rect 30x30 smd: 1(-28,0) 2(28,0)
  silkscreen extent -52,-24 52,24, body extent -34,-19 34,19, height 33
0603L [mm] "0603 from SM-752 data"
  rect 0.8x0.85 smd: 1(-0.7,0) 2(0.7,0)
  silkscreen extent -0.07,-0.33 0.07,0.33, body extent -0.87,-0.47 0.87,0.47, height 1
0603S [mil] "0603 from SM-752 data"
  rect 20x35 smd mask+0: 1(-30,0) 2(30,0)
  silkscreen extent -10,-17 10,17, body extent -34,-19 34,19, height 33
0612 [mm] "Panasonic recommended land pattern, fb97d03ed01.pdf dated April 2008"
  rect 0.65x2.75 smd: 1(-0.775,0) 2(0.775,0)
  silkscreen extent -1.1,-1.9 1.1,1.9, body extent -0.9,-1.7 0.9,1.7, height 0.85
0805_HV [mil] "0805 with 30mil clearance between pads"
  rect 50x63 smd: 1(-40,0) 2(40,0)
  silkscreen extent -74,-40 74,40, body extent -43,-29 43,29, height 57
0805L [mm] "0805 from SM-752 data"
  rect 1.1x1.4 smd: 1(-0.75,0) 2(0.75,0)
  body extent -1.1,-0.72 1.1,0.72, height 1.45
1206 [mm] "1206 from SM-752 data"
  rect 1.3x1.85 smd: 1(-1.45,0) 2(1.45,0)
  silkscreen extent -2.4,-1.21 2.4,1.21, body extent -1.7,-0.9 1.7,0.9, height 1.35
1206_190 [mm] "1206_190"
  rect 1.1x1.6 smd: 1(-1.7,0) 2(1.7,0)
  silkscreen extent -0.9,-1 0.9,1, body extent -1.75,-0.95 1.75,0.95, height 1.9
1210 [mm] "1210 from SM-752 data"
  rect 1.3x2.7 smd: 1(-1.45,0) 2(1.45,0)
  silkscreen extent -2.32,-1.57 2.32,1.57, body extent -1.7,-1.35 1.7,1.35, height 1.35
1210_280 [mm] "SMD, 2-Leads, Body 3.6x2.8mm, Height 2.8mm"
  rect 1.1x2.2 smd: 1(-1.65,0) 2(1.65,0)
  silkscreen extent -0.84,-1.4 0.84,1.4, body extent -1.8,-1.4 1.8,1.4, height 2.8
2220 [mm] "Chip Capacitor, Body 5.7x5.0mm, IPC Medium Density"
  rect 1.6x5.3 smd: 1(-2.6,0) 2(2.6,0)
  silkscreen extent -3.69,-2.94 3.69,2.94, body extent -2.95,-2.62 2.95,2.62, height 1.35
4527 [mil] "Vishay recommended land pattern"
  rect 155x230 smd: 1(-180,0) 2(180,0)
  silkscreen extent -275,-150 275,150, body extent -228,-138 228,138, height 96
AssemblyNote [mil] "Assembly Note"
Bumpon_SJ61A2 [mil] "3M Hemispherical Bumpon transparent"
  round 1 on Mech4: 0(0,0)
  silkscreen extent -192,-192 192,192, body extent -191,-192 193,192, height 250
DAP0038B_N [mil] "HTSSOP-38 Normal Density"
  oval 50x12 smd: 1(-150.5,230.32) 2(-150.5,204.73) 3(-150.5,179.14) 4(-150.5,153.55) 5(-150.5,127.95) 6(-150.5,102.36) 7(-150.5,76.77) 8(-150.5,51.18) 9(-150.5,25.59) 10(-150.5,0) 11(-150.5,-25.59) 12(-150.5,-51.18) 13(-150.5,-76.77) 14(-150.5,-102.36) 15(-150.5,-127.95) 16(-150.5,-153.55) 17(-150.5,-179.14) 18(-150.5,-204.73) 19(-150.5,-230.32) 20(150.5,-230.32) 21(150.5,-204.73) 22(150.5,-179.14) 23(150.5,-153.55) 24(150.5,-127.95) 25(150.5,-102.36) 26(150.5,-76.77) 27(150.5,-51.18) 28(150.5,-25.59) 29(150.5,0) 30(150.5,25.59) 31(150.5,51.18) 32(150.5,76.77) 33(150.5,102.36) 34(150.5,127.95) 35(150.5,153.55) 36(150.5,179.14) 37(150.5,204.73) 38(150.5,230.32)
  rect 140.55x208.27 smd: 39(0,0)
  silkscreen extent -169,-248 120,248, body extent -163,-251 165,251, height 47
DPAK [mm] "D-PAK, 3-Pads, Body 6.22x6.73mm (max), TO-252AA using nominal STEP model"
  rrect6% 2.6x1.6 smd: 1(-3.4,2.28) 3(-3.4,-2.28)
  rrect2% 6.2x5.8 smd paste-2.9: 4(3.4,0)
  silkscreen extent -4.5,-3.3 4.7,3.28, body extent -3.86,-3.29 5.84,3.29, height 2.48
DRC0010A [mm] "SON, 10-Leads, Body 3x3mm, Pitch 0.5mm, Thermal Pad 2.4x1.65mm, TI Recommended"
  oval 0.6x0.24 smd: 1(-1.4,1) 2(-1.4,0.5) 3(-1.4,0) 4(-1.4,-0.5) 5(-1.4,-1) 6(1.4,-1) 7(1.4,-0.5) 8(1.4,0) 9(1.4,0.5) 10(1.4,1)
  rect 1.65x2.4 smd paste-0.825: 11(0,0)
  Top Layer region: 0.135,-1.5 0.365,-1.5 0.365,-1.1 0.135,-1.1
  Top Layer region: -0.135,-1.1 -0.365,-1.1 -0.365,-1.5 -0.135,-1.5
  Top Layer region: -0.135,1.5 -0.365,1.5 -0.365,1.1 -0.135,1.1
  Top Layer region: 0.135,1.1 0.365,1.1 0.365,1.5 0.135,1.5
  silkscreen extent -1.7,-1.7 1.7,1.7, body extent -1.55,-1.55 1.55,1.55, height 1.01
DSG0008A [mm] "SON, 8-Leads, Body 2x2mm, Pitch 0.5mm, Thermal Pad 1.6x0.9mm, TI Recommended"
  rrect40% 0.5x0.25 smd: 1(-0.95,0.75) 2(-0.95,0.25) 3(-0.95,-0.25) 4(-0.95,-0.75) 5(0.95,-0.75) 6(0.95,-0.25) 7(0.95,0.25) 8(0.95,0.75)
  rrect11% 0.9x1.6 smd paste-0.45: 9(0,0)
  silkscreen extent -1.07,-1.15 1.07,1.15, body extent -1.05,-1.05 1.05,1.05, height 0.8
FC_1250x2500 [mm] "TH, 2-Leads, Dia 12.5mm, Lead Spacing 5mm"
  rect 1.4x1.4 hole 0.9: 1(-2.5,0)
  round 1.4 hole 0.9: 2(2.5,0)
  silkscreen extent -6.5,-6.5 6.5,6.5, body extent -6.45,-6.49 6.49,6.49, height 27.01
FCC_disclaimer [mil]
Fiducial10-20 [mm]
  round 1 smd mask+0.5: 1(0,0)
  Top Layer keep-out circle w1.178: c0,0 r0.5
IHLP-1616AB [mm] "Vishay Dale recommended land pattern.  Document 34261 rev 12-Sept-13"
  rect 1.65x2.3 smd: 1(-1.65,0) 2(1.65,0)
  silkscreen extent -2.45,-2.25 2.45,2.25, body extent -2.35,-2.16 2.35,2.16, height 1.2
IHLP-2525CZ [mm] "Vishay Dale recommended land pattern.  Document 34190 rev 10-Aug-06"
  rect 1.83x3.43 smd: 1(-2.77,0) 2(2.77,0)
  silkscreen extent -3.5,-3.3 3.5,3.3, body extent -3.62,-3.36 3.62,3.36, height 3
Keystone5002 [mil] "For Keystone 500x miniature loop terminals"
  round 80 hole 40: 1(0,0)
  silkscreen extent -58,-58 58,58, body extent -49,-49 49,49, height 182
Keystone5006 [mil] "Keystone Compact loops"
  round 87 hole 63: 1(0,0)
  silkscreen extent -70,-70 70,70, body extent -63,-63 62,63, height 225
"LG L29K_GREEN" [mm] "OSRAM"
  rect 0.8x0.8 smd paste-0.4: 1(-0.75,0) 2(0.75,0)
  silkscreen extent -0.1,-0.5 1.45,0.5, body extent -0.9,-0.45 0.9,0.45, height 0.67
Mill-Max_2505-2 [mil] "Mill-Max"
  round 100 hole 76 paste+0: 1(0,0)
  body extent -62,-63 62,62, height 187
Net-Tie_10milWide_30milLong [mil] "10mil net tie, no solder mask opening, no solder paste"
  rect 30x10 smd paste-5 mask-5: 1(-15,0) 2(15,0)
Pb-Free_Overlay_Small [mil]
  silkscreen extent -46,-46 46,46
Samtec_HTSW-102-07-G-S [mm] "Samtec 100mil, 1x2, 230 mil above insulator"
  rect 1.65x1.65 hole 1.016 mask+0: 1(-1.27,0)
  round 1.65 hole 1.016 mask+0: 2(1.27,0)
  silkscreen extent -3.3,-1.27 2.54,1.27, body extent -2.54,-1.27 2.54,1.27, height 8.38
SM_RADIAL_H13 [mm] "12.5 x 13.5mm:  Panasonic H13"
  rect 5.7x2 smd: 1(-4.85,0) 2(4.85,0)
  silkscreen extent -6.85,-6.85 6.85,6.85, body extent -6.85,-6.85 6.85,6.85, height 14
SML-LX0603SRW_SuperRed [mm] "Lumex Opto/Components Inc"
  rect 0.8x0.8 smd: 1(-0.75,0) 2(0.75,0)
  silkscreen extent 1.4,-0.53 1.78,0.53, body extent -0.92,-0.53 0.92,0.53, height 1.1
SOIC-8 [mm] "duplicate of SO-8.  SOIC, 8-Leads, Body 5.0x4.0mm (max), Pitch 1.27mm, IPC Medium Density"
  rrect17% 1.45x0.6 smd: 1(-2.725,1.905) 2(-2.725,0.635) 3(-2.725,-0.635) 4(-2.725,-1.905) 5(2.725,-1.905) 6(2.725,-0.635) 7(2.725,0.635) 8(2.725,1.905)
  silkscreen extent -3.5,-2.5 0.9,2.5, body extent -3,-2.45 3,2.45, height 1.63
SOT1289 [mm] "SMD, 3-Leads, Body 4.3x5.8mm"
  rect 1.6x1.44 smd paste-0.8 mask+0.1: 1(-1.065,2.78) 2(1.065,2.78)
  rect 3.8x4.96 smd paste-2.48 mask+0.1: 3(0,-1.02)
  silkscreen extent -2.65,-2.95 2.2,2.99, body extent -2.2,-2.95 2.2,2.95, height 0.87
SW_15451 [mm] "TH, 8-Leads, Body 12.6x12.6mm"
  rect 1.4x1.4 hole 0.9: 1(-5.08,5.08)
  round 1.4 hole 0.9: 2(5.08,5.08) 3(-5.08,2.54) 4(5.08,2.54) 5(-5.08,-2.54) 6(5.08,-2.54) 7(-5.08,-5.08) 8(5.08,-5.08)
  silkscreen extent -6.5,-6.25 6.25,6.25, body extent -6.25,-6.25 6.25,6.25, height 15.64
Tenma_SPC15354 [mm] "Insulated Banana Jack, Black"
  round 12 hole 6.858: 1(0,0)
  body extent -6.3,-6.34 6.35,6.34, height 8.8
Tenma_SPC15363 [mm] "Insulated Banana Jack, Red"
  round 12 hole 6.858: 1(0,0)
  body extent -6.3,-6.34 6.35,6.34, height 8.8
TI_Stacked_SolderMask_Small [mil]
  rect 900x250 smd paste-125 mask-125: 0(0,0)
TP_H045P075 [mm] "TP_H0.45P0.75"
  round 0.75 hole 0.45: 1(0,0)
TSW-112-07-G-S [mm] "Samtec 100mil, 1x12, 230 mil above insulator"
  rect 1.65x1.65 hole 1.016 mask+0: 1(-13.97,0)
  round 1.65 hole 1.016 mask+0: 2(-11.43,0) 3(-8.89,0) 4(-6.35,0) 5(-3.81,0) 6(-1.27,0) 7(1.27,0) 8(3.81,0) 9(6.35,0) 10(8.89,0) 11(11.43,0) 12(13.97,0)
  silkscreen extent -16.27,-1.27 15.24,1.27, body extent -15.24,-1.27 15.24,1.27, height 8.38
WE-HC6 [mm] "Wurth Electronik recommended land pattern"
  rect 3.85x4 smd: 1(-3.825,0) 2(3.825,0)
  silkscreen extent -6.2,-6.2 6.2,6.2, body extent -5.77,-5.37 5.75,5.35, height 5
ZWS0169A [mm] "BGA, 169-Leads, Body 12.00x12.00mmx1.40mm, Pitch 0.80mm"
  round 0.45 smd: A1(-4.8,4.8) A2(-4,4.8) A3(-3.2,4.8) A4(-2.4,4.8) A5(-1.6,4.8) A6(-0.8,4.8) A7(0,4.8) A8(0.8,4.8) A9(1.6,4.8) A10(2.4,4.8) A11(3.2,4.8) A12(4,4.8) A13(4.8,4.8) B1(-4.8,4) B2(-4,4) B3(-3.2,4) B4(-2.4,4) B5(-1.6,4) B6(-0.8,4) B7(0,4) B8(0.8,4) B9(1.6,4) B10(2.4,4) B11(3.2,4) B12(4,4) B13(4.8,4) C1(-4.8,3.2) C2(-4,3.2) C3(-3.2,3.2) C4(-2.4,3.2) C5(-1.6,3.2) C6(-0.8,3.2) C7(0,3.2) C8(0.8,3.2) C9(1.6,3.2) C10(2.4,3.2) C11(3.2,3.2) C12(4,3.2) C13(4.8,3.2) D1(-4.8,2.4) D2(-4,2.4) D3(-3.2,2.4) D4(-2.4,2.4) D5(-1.6,2.4) D6(-0.8,2.4) D7(0,2.4) D8(0.8,2.4) D9(1.6,2.4) D10(2.4,2.4) D11(3.2,2.4) D12(4,2.4) D13(4.8,2.4) E1(-4.8,1.6) E2(-4,1.6) E3(-3.2,1.6) E4(-2.4,1.6) E5(-1.6,1.6) E6(-0.8,1.6) E7(0,1.6) E8(0.8,1.6) E9(1.6,1.6) E10(2.4,1.6) E11(3.2,1.6) E12(4,1.6) E13(4.8,1.6) F1(-4.8,0.8) F2(-4,0.8) F3(-3.2,0.8) F4(-2.4,0.8) F5(-1.6,0.8) F6(-0.8,0.8) F7(0,0.8) F8(0.8,0.8) F9(1.6,0.8) F10(2.4,0.8) F11(3.2,0.8) F12(4,0.8) F13(4.8,0.8) G1(-4.8,0) G2(-4,0) G3(-3.2,0) G4(-2.4,0) G5(-1.6,0) G6(-0.8,0) G7(0,0) G8(0.8,0) G9(1.6,0) G10(2.4,0) G11(3.2,0) G12(4,0) G13(4.8,0) H1(-4.8,-0.8) H2(-4,-0.8) H3(-3.2,-0.8) H4(-2.4,-0.8) H5(-1.6,-0.8) H6(-0.8,-0.8) H7(0,-0.8) H8(0.8,-0.8) H9(1.6,-0.8) H10(2.4,-0.8) H11(3.2,-0.8) H12(4,-0.8) H13(4.8,-0.8) J1(-4.8,-1.6) J2(-4,-1.6) J3(-3.2,-1.6) J4(-2.4,-1.6) J5(-1.6,-1.6) J6(-0.8,-1.6) J7(0,-1.6) J8(0.8,-1.6) J9(1.6,-1.6) J10(2.4,-1.6) J11(3.2,-1.6) J12(4,-1.6) J13(4.8,-1.6) K1(-4.8,-2.4) K2(-4,-2.4) K3(-3.2,-2.4) K4(-2.4,-2.4) K5(-1.6,-2.4) K6(-0.8,-2.4) K7(0,-2.4) K8(0.8,-2.4) K9(1.6,-2.4) K10(2.4,-2.4) K11(3.2,-2.4) K12(4,-2.4) K13(4.8,-2.4) L1(-4.8,-3.2) L2(-4,-3.2) L3(-3.2,-3.2) L4(-2.4,-3.2) L5(-1.6,-3.2) L6(-0.8,-3.2) L7(0,-3.2) L8(0.8,-3.2) L9(1.6,-3.2) L10(2.4,-3.2) L11(3.2,-3.2) L12(4,-3.2) L13(4.8,-3.2) M1(-4.8,-4) M2(-4,-4) M3(-3.2,-4) M4(-2.4,-4) M5(-1.6,-4) M6(-0.8,-4) M7(0,-4) M8(0.8,-4) M9(1.6,-4) M10(2.4,-4) M11(3.2,-4) M12(4,-4) M13(4.8,-4) N1(-4.8,-4.8) N2(-4,-4.8) N3(-3.2,-4.8) N4(-2.4,-4.8) N5(-1.6,-4.8) N6(-0.8,-4.8) N7(0,-4.8) N8(0.8,-4.8) N9(1.6,-4.8) N10(2.4,-4.8) N11(3.2,-4.8) N12(4,-4.8) N13(4.8,-4.8)
  silkscreen extent -6.05,-6.05 6.05,6.05, body extent -6.05,-6.05 6.05,6.05, height 1.41

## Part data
C1 C15: "CAP, CERM, 10 µF, 50 V, +/- 10%, X7R, 2220"
C2 C3: "CAP, AL, 220 µF, 63 V, +/- 20%, 0.26 ohm, SMD"
C4 C8: "CAP, CERM, 1 µF, 25 V, +/- 5%, X7R, 1206_190"
C5 C6 C7: "CAP, AL, 560 µF, 50 V, +/- 20%, 0.05 ohm, TH"
C9 C19 C20: "CAP, CERM, 100 µF, 10 V, +/- 20%, X5R, 1210"
C10 C21: "CAP, CERM, 1 µF, 25 V, +/- 10%, X7R, 1206"
C11: "CAP, CERM, 1000 pF, 25 V, +/- 5%, C0G/NP0, 0603"
C12 C27: "CAP, CERM, 47 pF, 50 V, +/- 5%, C0G/NP0, 0603"
C13: "CAP, CERM, 470 pF, 50 V, +/- 10%, X7R, 0603"
C14 C26: "CAP, CERM, 0.22 µF, 25 V, +/- 10%, X5R, 0603"
C16: "CAP, CERM, 0.1 µF, 25 V, +/- 5%, X7R, 0603"
C17: "CAP, CERM, 4.7 µF, 25 V, +/- 10%, X5R, 0603_095"
C18 C24 C25 C28: "CAP, CERM, 0.01 µF, 25 V, +/- 10%, X7R, 0603"
C22 C23 C30: "CAP, CERM, 1000 pF, 50 V, +/- 10%, X7R, 0603"
C29: "CAP, CERM, 680 pF, 25 V, +/- 5%, C0G/NP0, 0402"
C31: "CAP, CERM, 0.012 µF, 25 V, +/- 5%, X7R, 0603"
C32: "CAP, CERM, 18 pF, 50 V, +/- 5%, C0G/NP0, 0603"
C33: "CAP, CERM, 27 pF, 50 V, +/- 5%, C0G/NP0, 0603"
C34: "CAP, CERM, 120 pF, 50 V, +/- 5%, C0G/NP0, 0603"
C35 C44 C47 C49 C51 C53 C55 C65 C67: "CAP, CERM, 4.7 µF, 25 V, +/- 10%, X5R, 0805"
C36 C45: "CAP, CERM, 0.1 µF, 16 V, +/- 10%, X7R, 0402"
C37: "CAP, CERM, 10 µF, 16 V, +/- 20%, X5R, 0603"
C38 C40 C41 C42 C43: "CAP, CERM, 2.2 µF, 16 V, +/- 10%, X5R, 0603"
C39 C46 C48 C50 C52 C54 C56 C66 C68: "CAP, CERM, 47 µF, 10 V, +/- 10%, X7R, 1210"
C57 C58 C59 C60 C61 C62 C63 C64: "CAP, CERM, 2.2 µF, 6.3 V, +/- 20%, X5R, 0402"
C69: "CAP, CERM, 0.1 µF, 16 V, +/- 10%, X5R, 0603"
C70: "CAP, CERM, 1 µF, 16 V, +/- 10%, X5R, 0603"
C71: "CAP, CERM, 220 pF, 50 V, +/- 10%, X7R, 0603"
C72: "CAP, CERM, 0.01 µF, 10 V, +/- 10%, X5R, 0402"
C73: "CAP, CERM, 10 µF, 25 V, +/- 10%, X5R, 0805"
C74 C75 C76 C82 C83: "CAP, CERM, 10 µF, 6.3 V, +/- 10%, X7R, 0805"
C77: "CAP, CERM, 0.1 µF, 25 V, +/- 10%, X8R, 0603"
C78: "CAP, CERM, 10 pF, 100 V, +/- 5%, C0G/NP0, 0603"
C79 C80 C81: "CAP, CERM, 1000 pF, 50 V, +/- 1%, C0G/NP0, 0603"
D1 D2: "Diode, Schottky, 45 V, 15 A, CFP15"
D3: "LED, Super Red, SMD"
D4: "LED, Green, SMD"
FID1 FID2 FID3 FID4 FID5 FID6: "Fiducial mark.  There is nothing to buy or mount."
H1 H2 H3 H4: "Bumpon, Hemisphere, 0.375 X 0.235, Black"
J1: "BANANA JACK, SOLDER LUG, RED, TH"
J2: "BANANA JACK, SOLDER LUG, BLACK, TH"
J3: "Header, 100mil, 12x1, Gold, TH"
J4: "Header, 100mil, 2x1, Gold, TH"
J5: library part HTSW-102-07-G-S, "Header, 100mil, 2x1, Gold, TH"
L1: "Inductor, Shielded Drum Core, Superflux, 1.8uH, 16A, 0.0035 ohm, SMD"
L2: "Inductor, Shielded Drum Core, Powdered Iron, 10uH, 3A, 0.102 ohm, SMD"
L3: "Inductor, Shielded Drum Core, Powdered Iron, 4.7uH, 5.5A, 0.037 ohm, SMD"
L4 L5 L6 L7 L8 L9 L10 L11 L12: "Inductor, Shielded Drum Core, Powdered Iron, 1 µH, 4 A, 0.05 ohm, SMD"
Logo1: library part TI_Logo, "Texas Instrument Corporate Signature"
Logo2: library part Pb-Free
Logo3: library part FCC_disclaimer, "FCC_disclaimer"
NT1 NT2 NT3 NT4: "Single point connection between nets."
Q1: "MOSFET, P-CH, -60 V, -50 A, DPAK"
Q2 Q3 Q5 Q6: "MOSFET, N-CH, 40 V, 19 A, SOIC-8"
Q4: "MOSFET, N-CH, 40 V, 42 A, DPAK"
R1: "RES, 0.022, 1%, 1 W, 0612"
R2 R9: "RES, 10.0, 1%, 0.1 W, 0603"
R3: "RES, 432 k, 1%, 0.1 W, 0603"
R4: "RES, 1.50 k, 1%, 0.1 W, 0603"
R5 R11: "RES, 82.5 k, 1%, 0.1 W, 0603"
R6: "RES, 0.015, 1%, 3 W, 4527"
R7: "RES, 49.9 k, 0.1%, 0.1 W, 0603"
R8: "RES, 0.015, 1%, 1 W, 0612"
R10: "RES, 255 k, 1%, 0.1 W, 0603"
R12: "RES, 1.0 k, 5%, 0.1 W, 0603"
R13: "RES, 39 k, 5%, 0.1 W, 0603"
R14: "RES, 27.0 k, 0.5%, 0.1 W, 0603"
R15 R20 R25 R26 R29 R30: "RES, 10.0 k, 1%, 0.1 W, 0603"
R16 R17 R18 R19: "RES, 2.2 k, 5%, 0.063 W, 0402"
R21 R22 R23 R24: "RES, 0, 5%, 0.063 W, 0402"
R27: "RES, 100 k, 5%, 0.1 W, 0603"
R28: "RES, 10.0, 0.1%, 0.1 W, 0603"
R31: "RES, 49.9, 1%, 0.1 W, 0603"
R32: "RES, 806, 1%, 0.1 W, 0603"
S1: library part 15451, "Switch, 4PST, 0.25 A, 120 V, TH"
TP1 TP5 TP16 TP17 TP18 TP19 TP20 TP21 TP22 TP23 TP24 TP25 TP26 TP27: library part 2505-2-00-44-00-00-07-0, "PCB Pin, Swage Mount, TH"
TP2 TP7 TP9 TP10 TP13 TP14 TP15: library part TP_H0.45P0.75, "Testpoint"
TP3 TP4: library part 5006, "Test Point, Compact, Black, TH"
TP6 TP8 TP11 TP12: library part 5002, "Test Point, Miniature, White, TH"
U1: "LOW IQ, SINGLE BOOST, DUAL SYNCHRONOUS BUCK CONTROLLER, DAP0038B"
U2: "Automotive Power Management Unit (PMU) for Processor, ZWS0169A"
U3: "5.5-V, 4-A, 16-mO On-Resistance Load Switch, DSG0008A"
U4: "Single Output Automotive LDO, 3 A, 2.3 to 3.5 V Input, with DDR Termination, 10-pin SON (DRC), -40 to 125 degC, Green (RoHS & no Sb/Br)"
ZZ1 ZZ2 ZZ3 ZZ4: library part AssemblyNote

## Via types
v1: diameter 22, hole 10, Top Layer to Bottom Layer, tented both sides, 258 vias
v2: diameter 26, hole 10, Top Layer to Bottom Layer, tented both sides, 214 vias
v3: diameter 17.72, hole 8, Top Layer to Bottom Layer, tented both sides, 162 vias
v4: diameter 17.7, hole 7.8, Top Layer to Bottom Layer, 104 vias
v5: diameter 19.68, hole 7.87, Top Layer to Bottom Layer, 14 vias
v6: diameter 18, hole 8, Top Layer to Bottom Layer, tented both sides, 5 vias

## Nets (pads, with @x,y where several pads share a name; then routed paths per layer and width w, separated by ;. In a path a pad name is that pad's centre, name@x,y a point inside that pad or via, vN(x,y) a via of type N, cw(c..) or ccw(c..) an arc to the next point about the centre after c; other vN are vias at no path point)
3V3: C19.1 C20.1 C21.1 C35.2 C37.1 C41.1 C42.1 C43.1 C44.2 C47.2 C49.2 C51.2 C53.2 C55.2 C65.2 C67.2 C70.1 C73.1 NT4.2 R8.2 R10.2 R27.2 TP3.1 U2.A11 U2.B3 U2.C4 U2.C5 U2.C7 U2.D11 U2.D12 U2.D13 U2.E1 U2.E2 U2.E3 U2.F1 U2.F2 U2.F3 U2.G11 U2.G12 U2.G13 U2.H11 U2.H12 U2.H13 U2.J1 U2.J2 U2.J3 U2.L12 U2.L13 U2.M4 U2.M6 U2.M8 U2.M9 U2.N3 U2.N4 U2.N6 U2.N8 U2.N9 U3.1 U3.2 U4.10 | length 1123.8
  Top Layer w8: v1(3596.63,1696.63) 3674.29,1618.97 U2.A11@3690.02,1618.98
  Top Layer w9: R27.2@2795,2671.5 2795,2720
  Signal Layer 2 w10: v1(2785,1710) 2825,1710 2870,1755 v1(2870,2285)
  Signal Layer 3 w10: 3740,1538.22 3760,1518.22 3760,1499.98 v4(3753.02,1492.99)
  Bottom Layer w8: v1(3605,1270) 3624.54,1270 v4(3721.52,1367.01)
  Bottom Layer w10: R10.2@2785,1676.5 v1(2785,1710)
  Bottom Layer w12: v4(3753.02,1492.99) C37.1@3772,1493
  Bottom Layer w15: v4(3753.02,1492.99) C37.1@3772,1493
  Bottom Layer w18: v4(3753.02,1398.5) v4(3753.02,1430)
  other v1: 2495,140 2540,140 2580,140 2495,190 2540,190 2580,190 3160,2215 3160,2255 2945,2295 2980,2295 3020,2295 3065,2295 3100,2295 3135,2295 2775,2715 2715,2750 2745,2750 2775,2750
  other v3: 4230,1189 4230,1207 4023,1799 4043,1799
  other v4: 3816.01,1304.02 3847.5,1304.02 3941.99,1304.02 3816.01,1335.51 3847.5,1335.51 3941.99,1335.51 3816.01,1367.01 3847.5,1367.01 3941.99,1367.01 4036.48,1461.5 4067.98,1461.5 4036.48,1524.49 4067.98,1524.49 4036.48,1555.98 4067.98,1555.98 3784.51,1618.98 3879,1618.98 3910.5,1618.98 3784.51,1650.47 3879,1650.47 3910.5,1650.47 3784.51,1681.97 3879,1681.97 3910.5,1681.97
3V3_SW: C36.2 C69.1 R16.2 R17.2 R18.2 R19.2 R26.2 TP5.1 U2.D9 U3.7 U3.8 | length 6893.6
  Top Layer w10: v1(2785,2455) R26.2@2785,2488.5 ; R18.2@4200,926.38 R19.2@4240,926.38
  Top Layer w15: R17.2@4238.62,815 4240,816.38 v1(4240,899) R19.2@4240,926.38
  Signal Layer 2 w10: TP5.1@2090,215 2500,625 2500,1265 2275,1490 2275,2000 2585,2310 2710,2310 2785.03,2385.03 v1(2785,2455)
  Signal Layer 2 w15: 3125,100 3125,185
  Signal Layer 2 w20: TP5.1@2060,190 2180,70 3095,70 3125,100 ; 3125,185 3190,250 4085,250 4265,430 4265,650 4240,675 v1(4240,899)
  Bottom Layer w4: C36.2@3795,1555 3795,1544 3798,1541 3950,1541 3958,1533 3958,1446
  Bottom Layer w12: 3958,1446 3989,1415
  Bottom Layer w15: 3989,1415 4056,1415 4166,1305 4166,1116 4263,1019 4263,922 v1(4240,899)
  other v4: 3784.51,1555.98
5V0: C9.1 C10.1 C16.2 C38.2 C40.1 C72.1 NT2.2 R1.2 R3.2 TP4.1 U1.37 U2.A6 U2.A9 U2.A10 U3.4 | length 1860.2
  Top Layer w10: v1(2325,1635) 2323.5,1633.5 C16.2@2323.5,1600 2325,1600 2365,1560 2395,1560 2407.27,1547.73 U1.37@2407.27,1511
  Signal Layer 2 w10: v1(2325,1635) 2355,1665 2530,1665 2652,1543 3207,1543 3277.5,1472.5 ; v1(2825,1010) 2850,1010 2870,990 v1(2870,460)
  Bottom Layer w10: R3.2@2785,1043.5 2795,1033.5 2795,1035 v1@2822.5,1007.5
  other v1: 2380,315 2350,325 2380,345 2350,355 2950,460 2990,460 3030,460 3037,487 3037,514
  other v3: 3632.95,1443.78 3632.95,1463.46 3638.03,1587.5 3638.03,1615
BOOT0: R22.1 R24.2 U2.L3 | length 666.9
  Top Layer w10: R24.2@4290,923.62 v1(4290,955) R22.1@4290,986.38
  Signal Layer 2 w4: v4(4004.98,1367.01) 4027.96,1390 4076,1390
  Signal Layer 2 w8: 4076,1390 4251,1215 4251,1039 4290,1000 v1(4290,955)
BOOT1: R21.1 R23.2 U2.K7 | length 806.3
  Top Layer w10: R23.2@4340,923.62 v1(4340,955) R21.1@4340,986.38
  Signal Layer 2 w4: v4(3973.49,1492.99) 3988.65,1477.84 4080.42,1477.84
  Signal Layer 2 w8: 4080.42,1477.84 4340,1218.26 v1(4340,955)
